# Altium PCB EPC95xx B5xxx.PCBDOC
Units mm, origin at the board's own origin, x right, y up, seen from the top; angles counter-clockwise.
Board outline 50 x 37 mm, 6 copper layers (Top Layer, Mid-Layer 1, Mid-Layer 2 (Gnd), Mid-Layer 3 (54V), Mid-Layer 4, Bottom Layer), stack 1.55 mm thick; 55 components, 32 nets, 377 pads, 537 vias.
Unrouted connection lines stored in the file: 17.
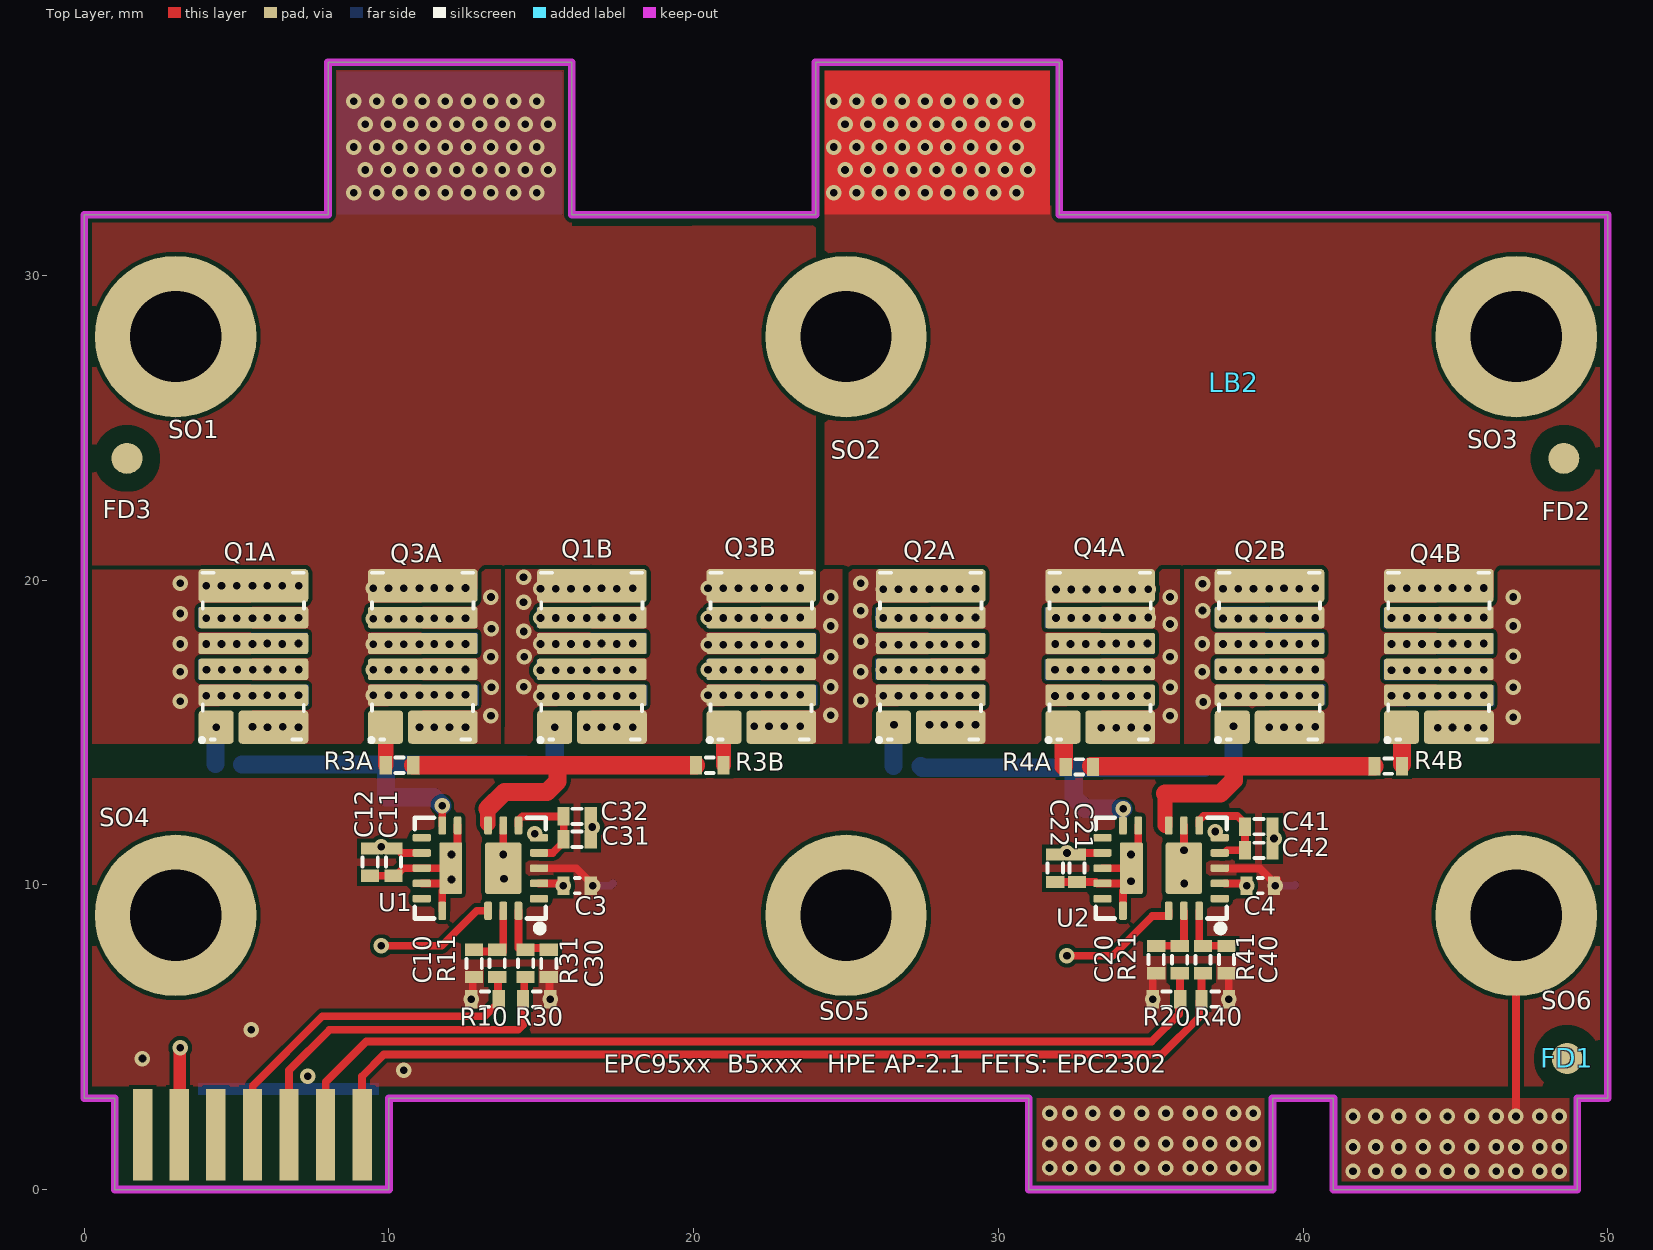
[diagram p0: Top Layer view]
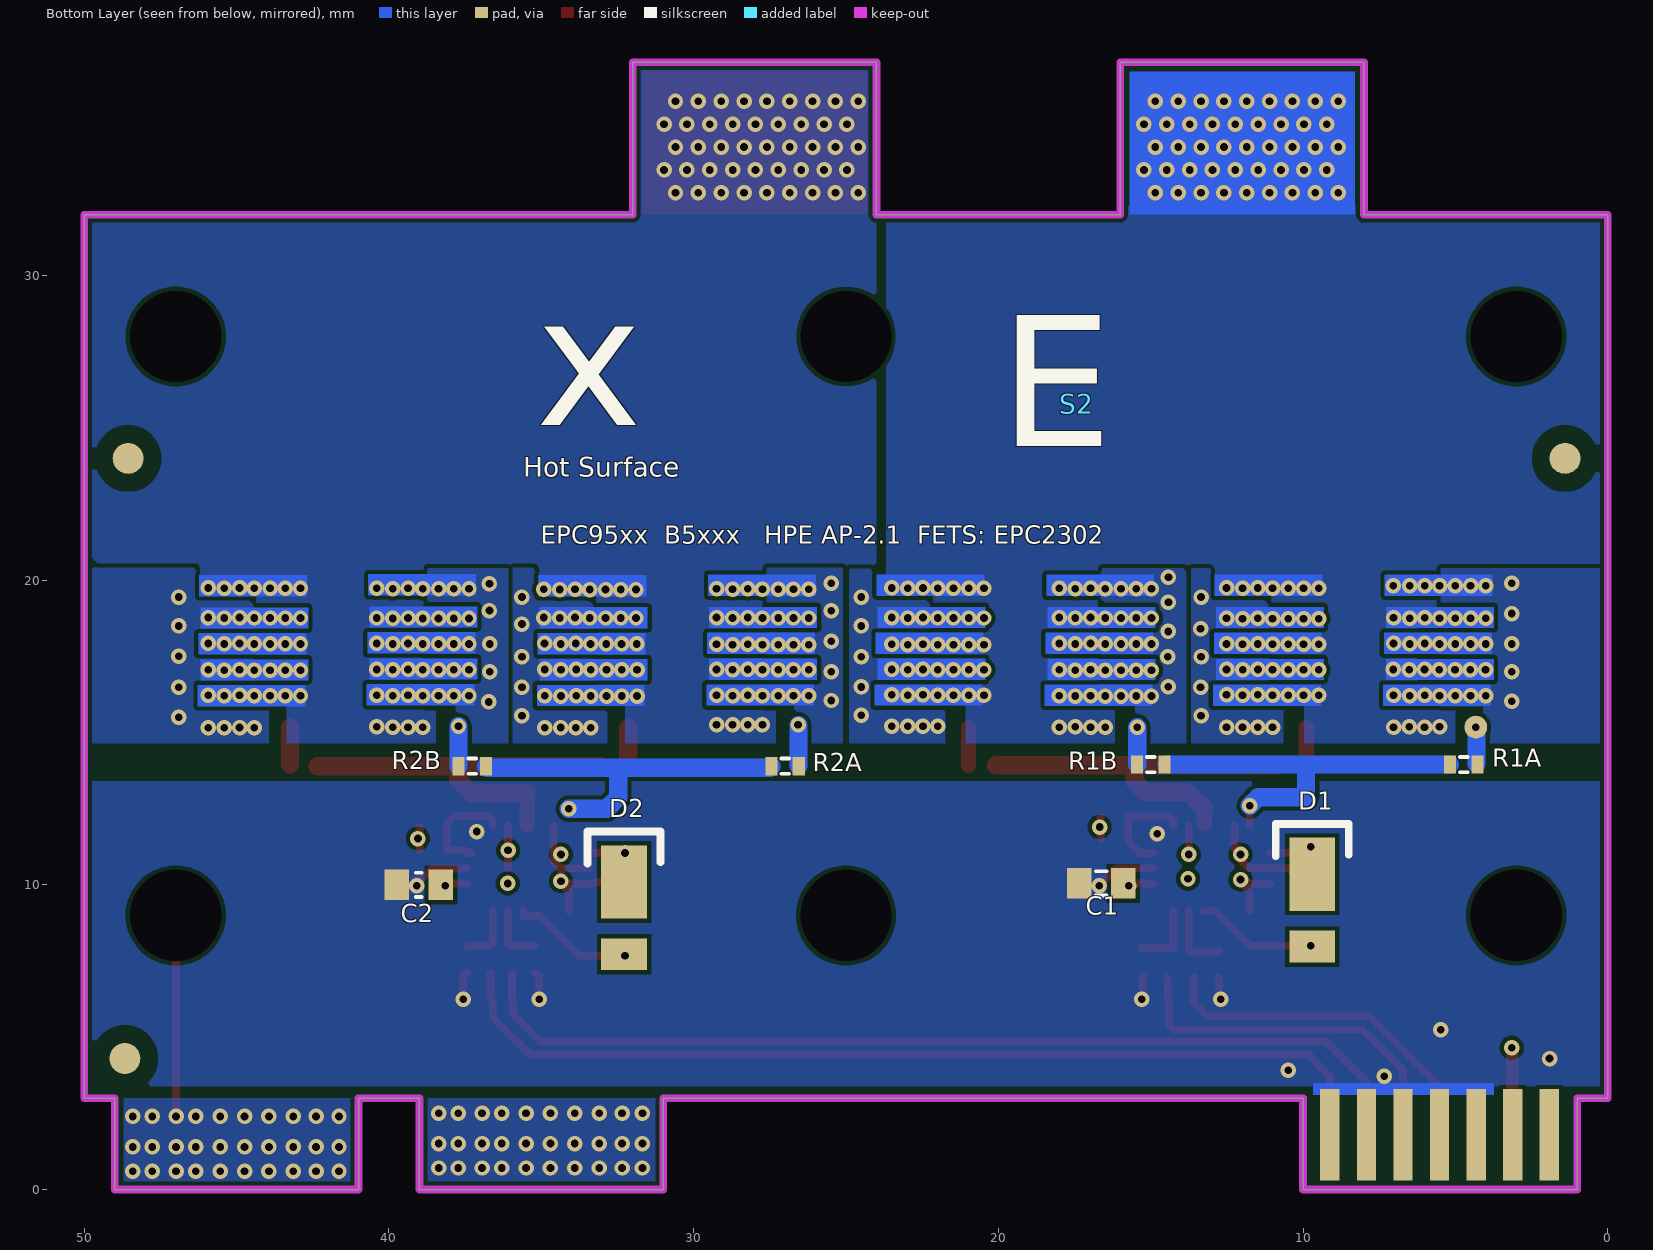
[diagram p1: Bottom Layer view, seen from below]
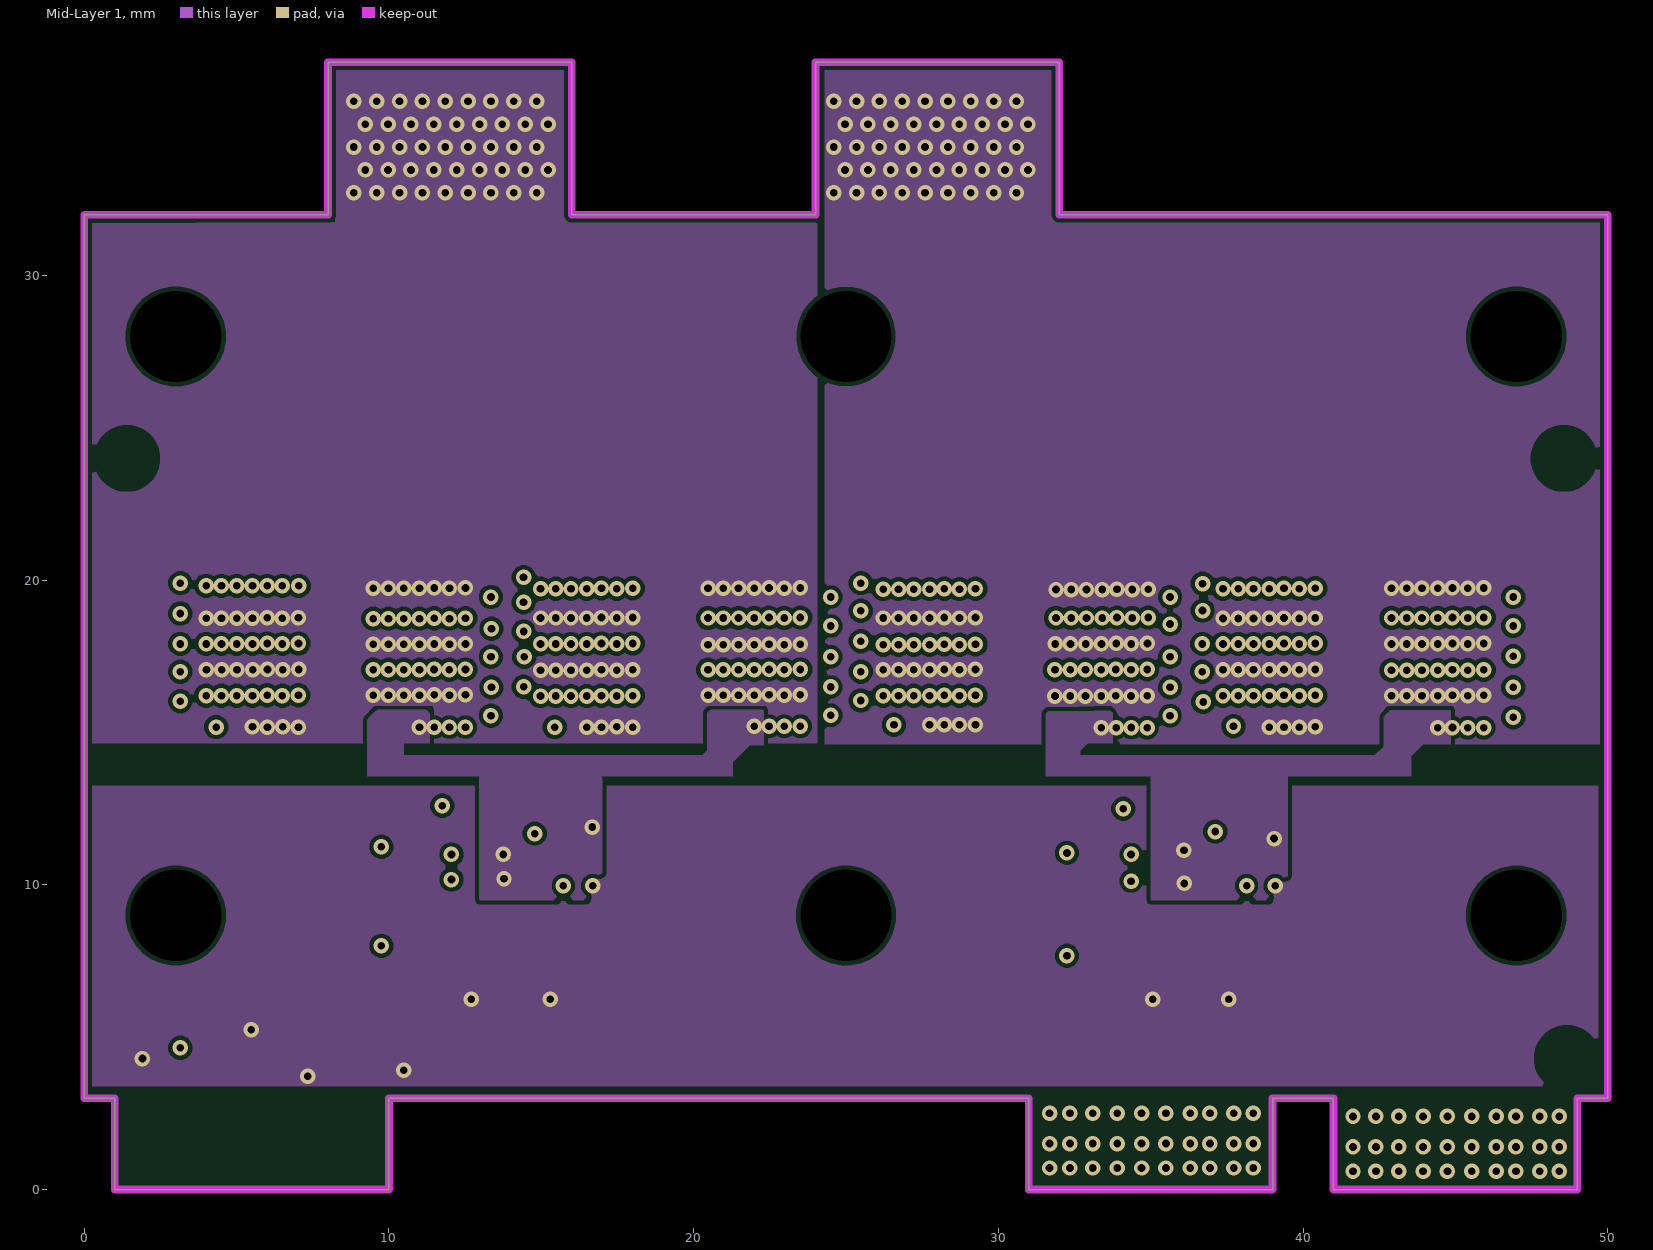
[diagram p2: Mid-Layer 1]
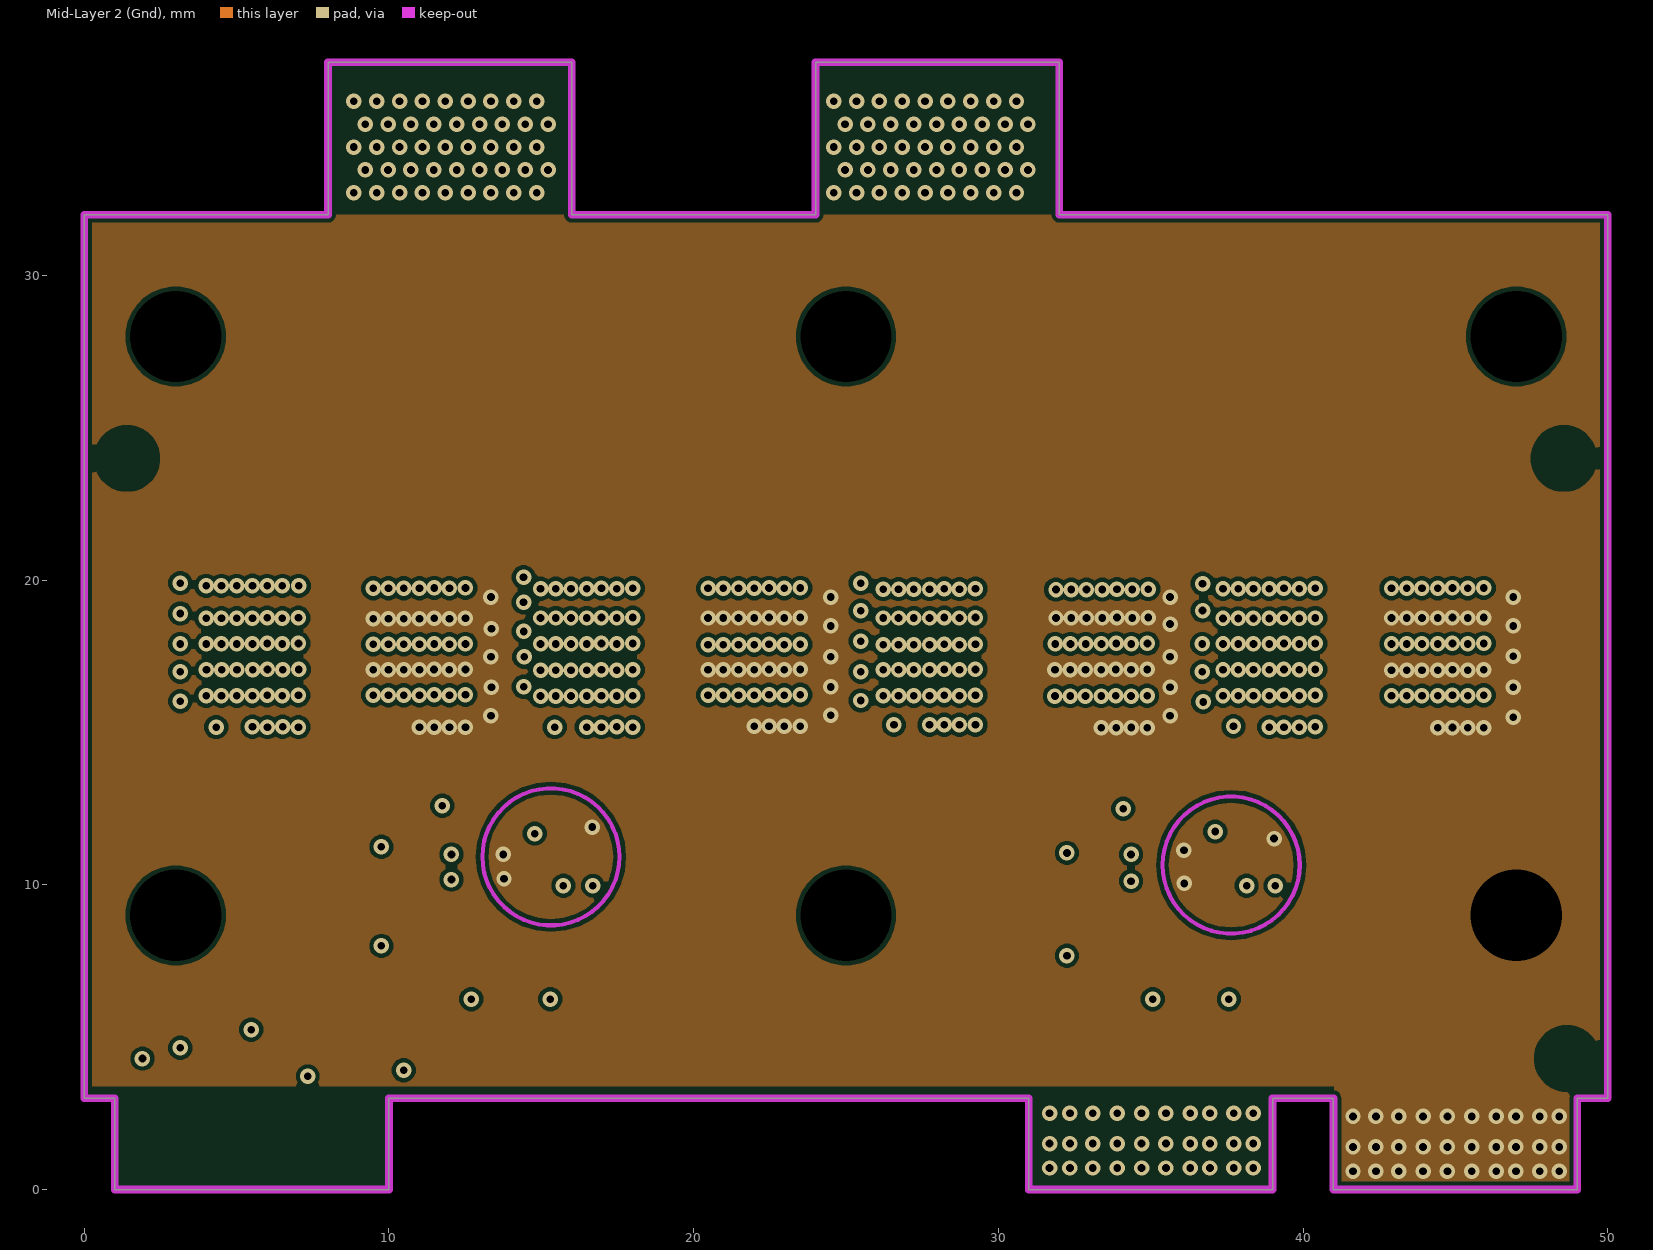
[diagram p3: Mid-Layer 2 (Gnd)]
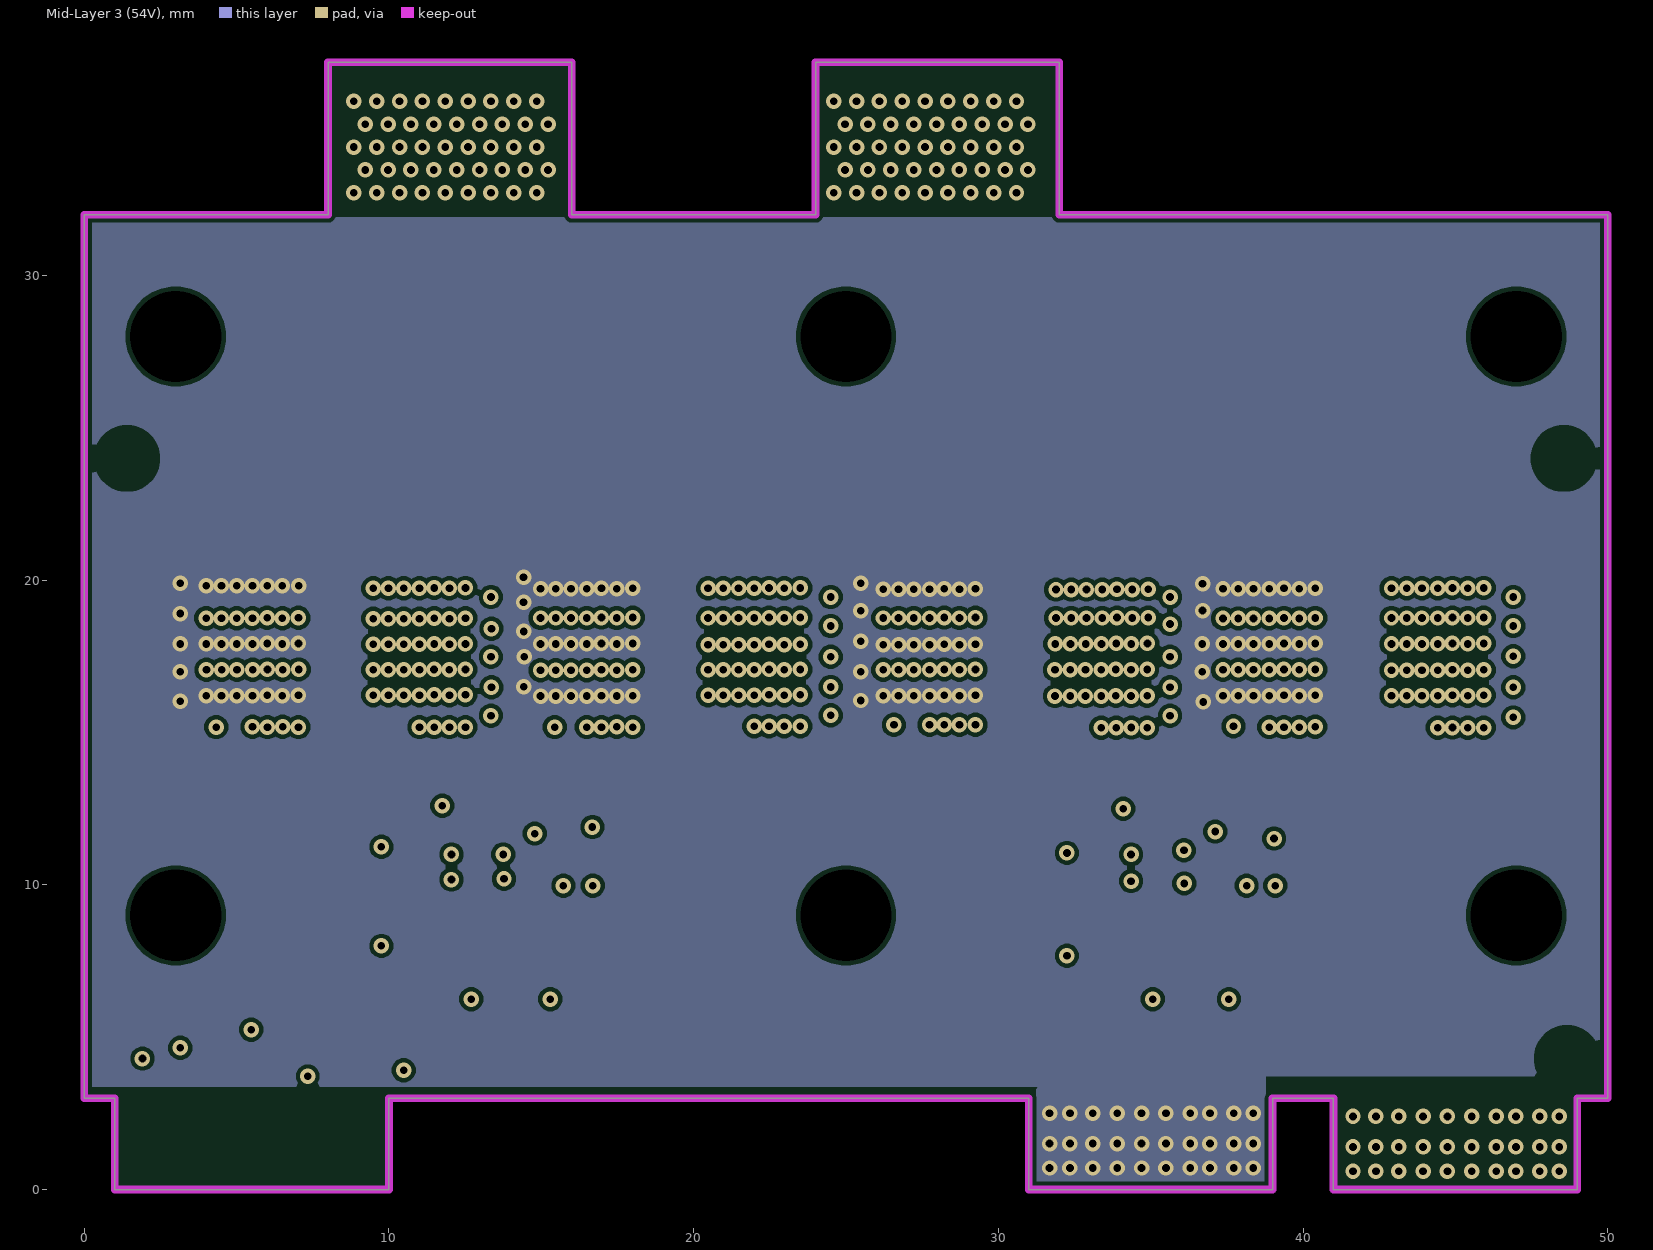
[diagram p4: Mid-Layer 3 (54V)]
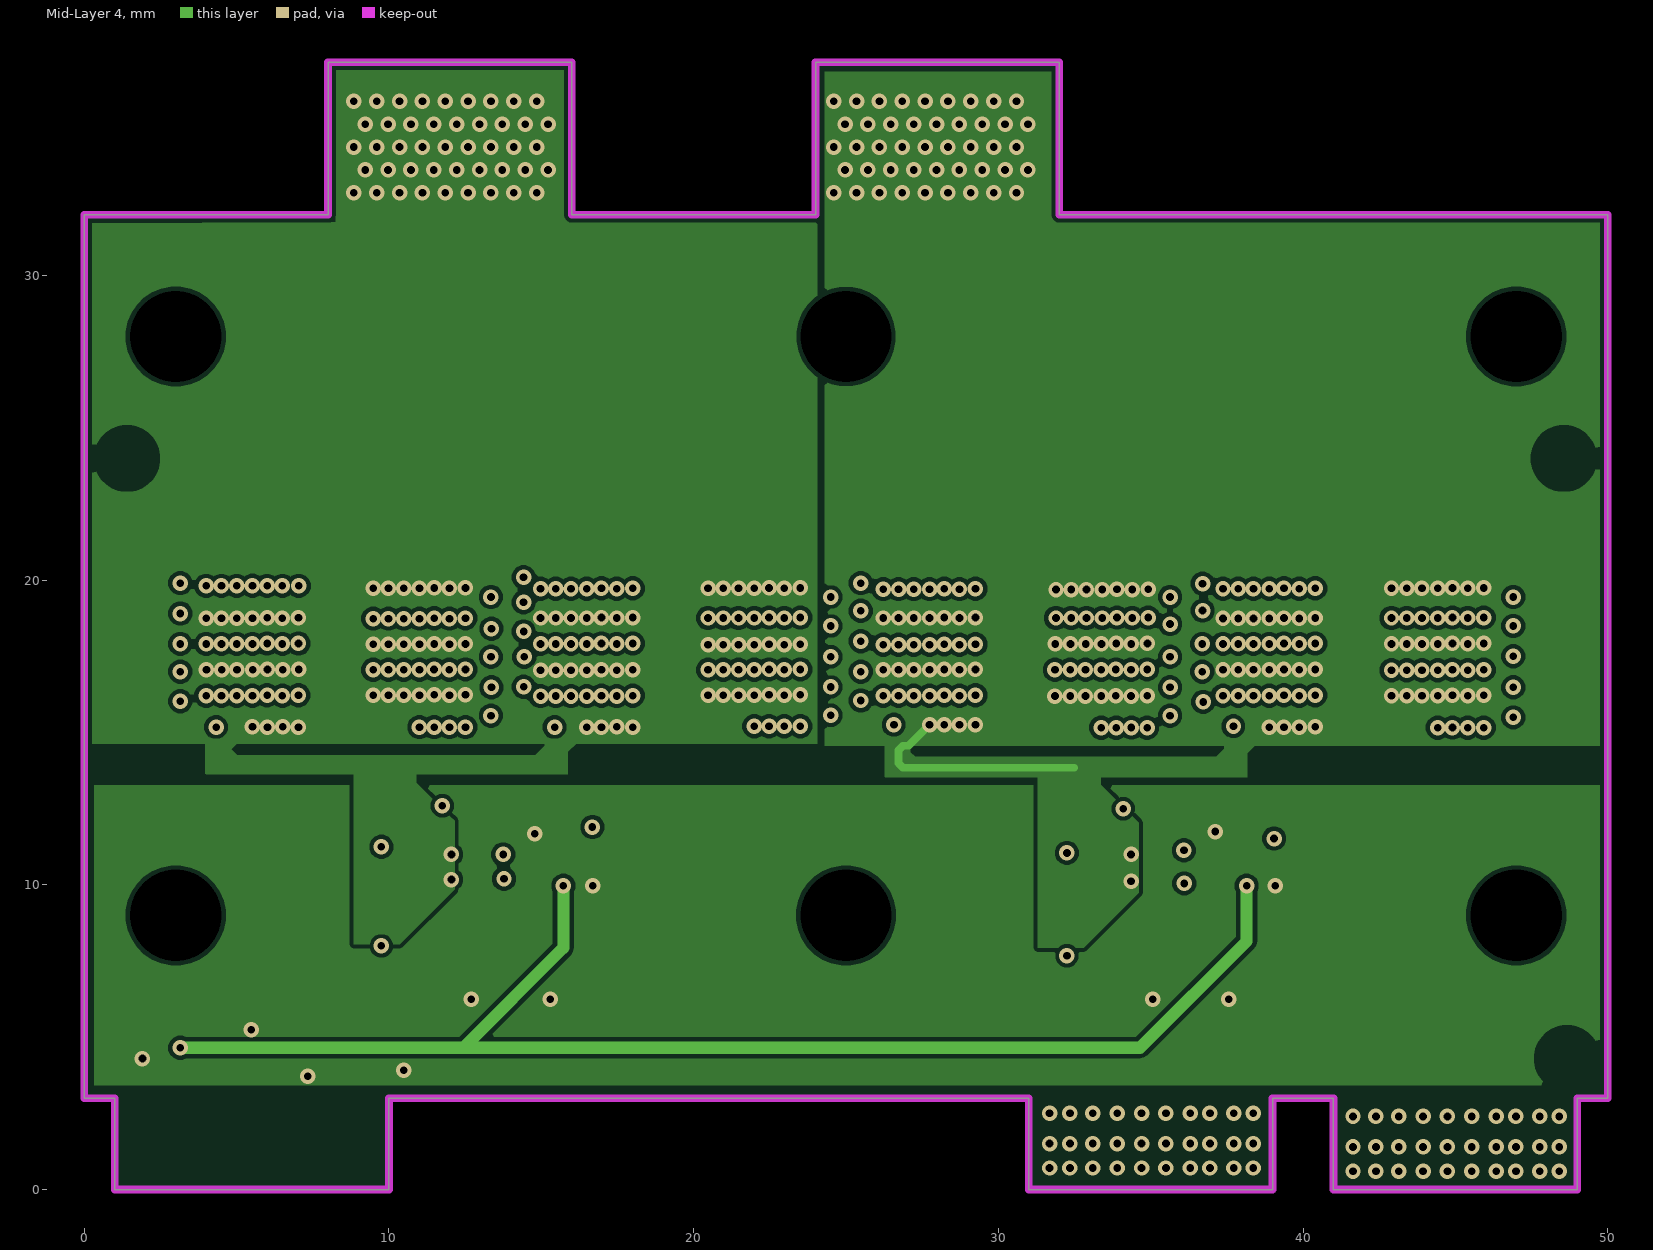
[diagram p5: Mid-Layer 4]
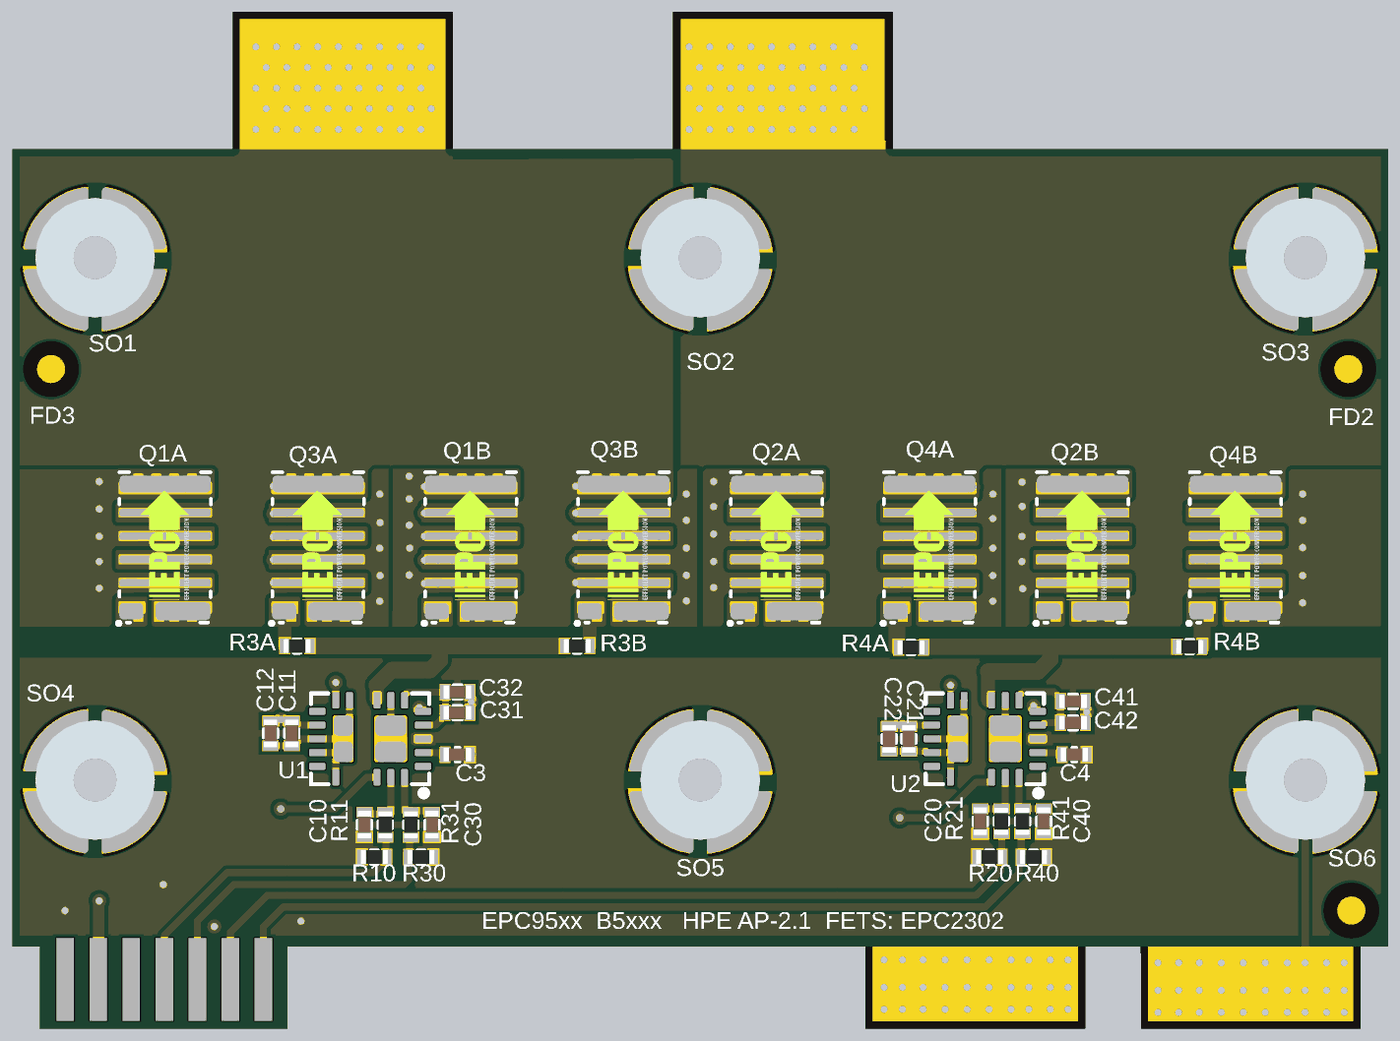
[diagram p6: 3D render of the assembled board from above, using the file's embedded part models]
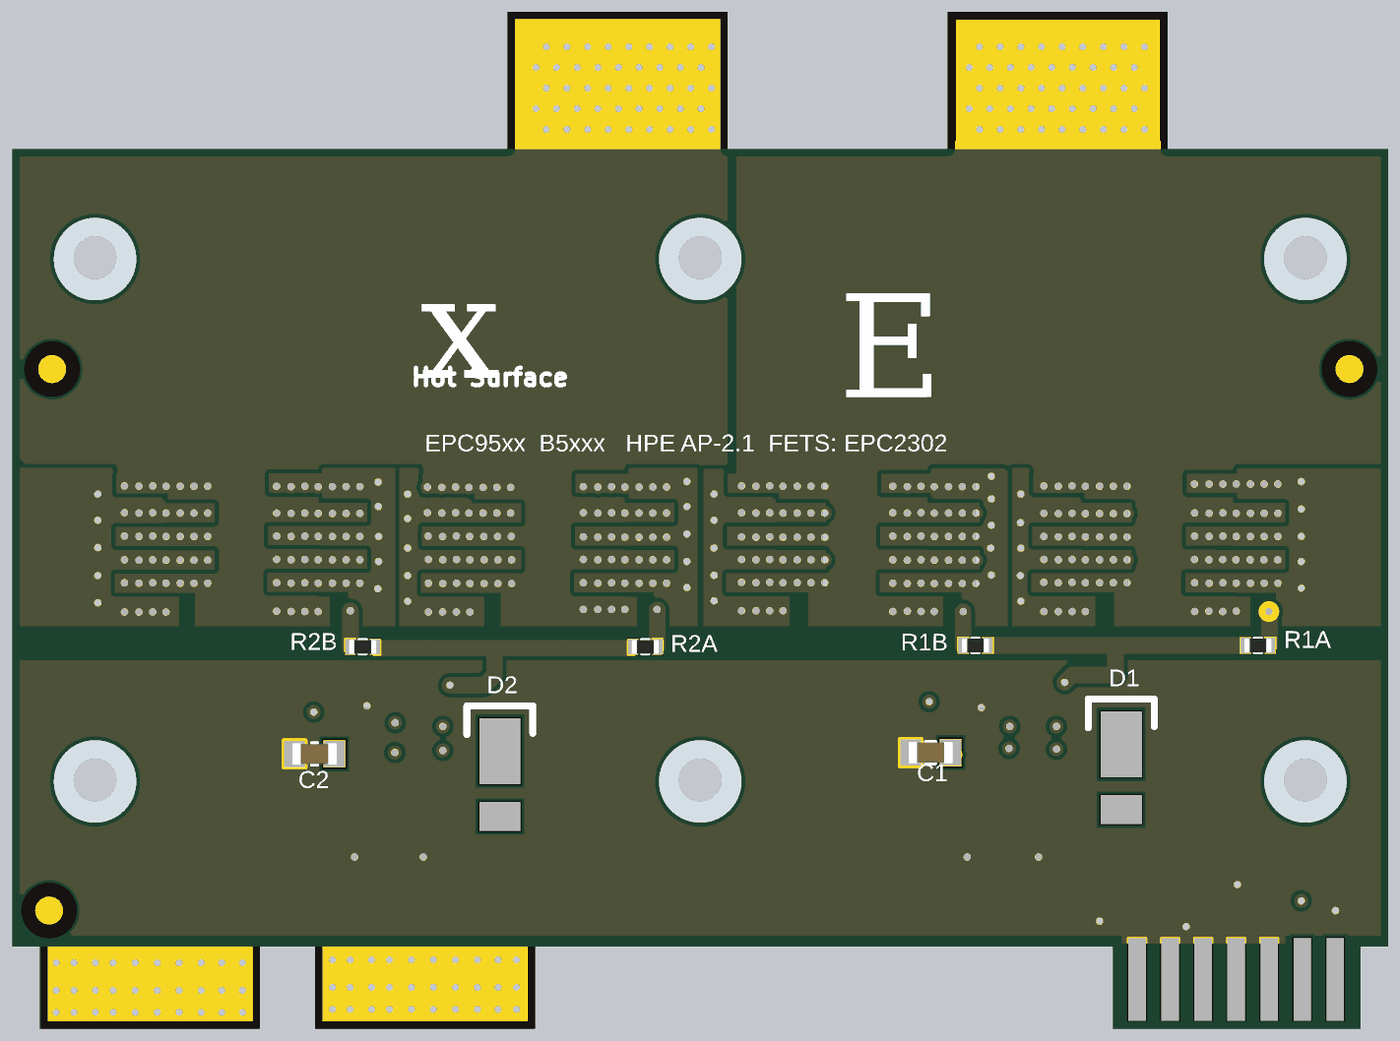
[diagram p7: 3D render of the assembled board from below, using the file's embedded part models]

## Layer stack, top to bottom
Top Solder: solder mask 0.0102, Solder Resist, Dk 3.5
Top Layer: signal copper 0.0711
Dielectric 1: core 0.127, FR-4, Dk 4.8
Mid-Layer 1: signal copper 0.0711
Dielectric 2: prepreg 0.309, PP-006, Dk 4.1
Mid-Layer 2 (Gnd): signal copper 0.07
Dielectric 3: prepreg 0.254, FR-4, Dk 4.8
Mid-Layer 3 (54V): signal copper 0.07
Dielectric 4: prepreg 0.309, PP-006, Dk 4.1
Mid-Layer 4: signal copper 0.0711
Dielectric 5: core 0.127, FR-4, Dk 4.8
Bottom Layer: signal copper 0.0711
Bottom Solder: solder mask 0.0102, Solder Resist, Dk 3.5

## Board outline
24,37 32,37 32,32 50,32 50,3 49,3 49,0 41,0 41,3 39,3 39,0 31,0 31,3 10,3 10,0 1,0 1,3 0,3 0,32 8,32 8,37 16,37 16,32 24,32

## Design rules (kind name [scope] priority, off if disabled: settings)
AssemblyTestPointUsage [All] p1 off:
AssemblyTestpoint [All] p1 off: testpointundercomponent=TRUE minsize=1.016 maxsize=2.54 preferedsize=1.524 minholesize=0 maxholesize=1.016 preferedholesize=0.813 testpointgrid=0.025 usegrid=TRUE gridtolerance=0 allowsidetop=TRUE allowsidebottom=TRUE
Clearance [All] p1: gap=0.135 ignorepadtopadclearanceinfootprint=TRUE // Everything else
Clearance Keepout [(OnLayer('Keep-Out Layer'))] p2: gap=0.508 ignorepadtopadclearanceinfootprint=TRUE except(0: Arc-Hole Track-Hole SMDPad-Hole THPad-Hole Via-Hole Fill-Hole Poly-Hole Region-Hole Text-Hole)
ComponentClearance [All] p1: gap=0.127 collisioncheckmode=3 verticalgap=0 showdistances=FALSE
FabricationTestPointUsage [All] p1 off: valid=0 allowmultiple=FALSE
FabricationTestpoint [All] p1 off: side=3 testpointundercomponent=TRUE minsize=1.016 maxsize=2.54 preferedsize=1.524 minholesize=0 maxholesize=1.016 preferedholesize=0.813 testpointgrid=0.025 allowsidetop=TRUE allowsidebottom=TRUE usegrid=TRUE gridtolerance=0
FanoutControl Fanout_BGA [IsBGA] p1 off: bgadir=Out bgaviamode=Centered fanoutstyle=Auto fanoutdirection=Alternating viagrid=0.025 // Fanout_BGA (Default Rule)
FanoutControl Fanout_LCC [IsLCC] p2 off: bgadir=Out bgaviamode=Centered fanoutstyle=Auto fanoutdirection=Alternating viagrid=0.025 // Fanout_LCC (Default Rule)
FanoutControl Fanout_SOIC [IsSOIC] p3 off: bgadir=Out bgaviamode=Centered fanoutstyle=Auto fanoutdirection=Alternating viagrid=0.025 // Fanout_SOIC (Default Rule)
FanoutControl Fanout_Small [(CompPinCount < 5)] p4 off: bgadir=Out bgaviamode=Centered fanoutstyle=Auto fanoutdirection=OutThenIn viagrid=0.025 // Fanout_Small (Default Rule)
FanoutControl Fanout_Default [All] p5 off: bgadir=Out bgaviamode=Centered fanoutstyle=Auto fanoutdirection=Alternating viagrid=0.025 // Fanout_Default (Default Rule)
HoleSize [All] p1: absolutevalues=TRUE maxlimit=3 minlimit=0.025 maxpercent=80.000 minpercent=20.000
HoleToHoleClearance [All] p1 off: gap=0.254 allowstackedmicrovias=TRUE
MinimumSolderMaskSliver [All] p1: minsoldermaskwidth=0.02
NetAntennae [All] p1 off: netantennaetolerance=0
PlaneConnect [All] p1: planeconnectstyle=Direct reliefexpansion=0.508 reliefentries=4 reliefconductorwidth=0.254 reliefairgap=0.254
PolygonConnect [All] p1: connectstyle=Direct reliefconductorwidth=0.254 reliefentries=4 polygonreliefangle="90 Angle" airgapwidth=0.254
RoomDefinition "EPC95xx B5xxx" [InComponentClass('EPC95xx B5xxx')] p1: confinementstyle=ConfineIn formatcopy=TRUE lockcomponents=FALSE outline 0,-0.3 50.35,-0.3 50.35,37 0,37
RoutingVias [All] p1: holewidth=0.711 width=1.27 viastyle="Through Hole" minholewidth=0.203 minwidth=0.254 maxholewidth=1.27 maxwidth=2.54
SilkToSilkClearance [All] p1: silktosilkclearance=0.025
SilkToSolderMaskClearance SilkscreenOverComponentPads [IsPad OR IsVia OR OnLayer('Top Solder') vs OnLayer('Top Overlay')] p1: minsilkscreentomaskgap=0.025 clearancetoexposedcopper=TRUE
SilkToSolderMaskClearance SilkscreenOverComponentPads_1 [IsPad OR IsVia OR OnLayer('Bottom Solder') vs OnLayer('Bottom Overlay')] p2: minsilkscreentomaskgap=0.025 clearancetoexposedcopper=TRUE
SolderMaskExpansion [All] p1: expansion=0.051 istentingtop=FALSE
Width [All] p1: maxlimit=254 minlimit=0.127 preferedwidth=0.254
13 further rules are at their usual default settings.

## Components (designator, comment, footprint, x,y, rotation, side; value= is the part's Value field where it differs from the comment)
C1 "C1608X5R1E106M080AC" CC0603 16.625,10.048 r180 bottom value=10uF
C2 "C1608X5R1E106M080AC" CC0603 39.024,10 r180 bottom value=10uF
C3 "UMK105ABJ474KV-F" CC0402 16.173,9.975 r180 top value=470nF
C4 "UMK105ABJ474KV-F" CC0402 38.6,9.975 r180 top value=470nF
C10 "C1005C0G2A221J050BA" CC0402 12.792,7.425 r270 top value=220pF
C11 "C1005X5R1E474K050BB" CC0402 10.15,10.75 r270 top value=470nF
C12 "C1005X5R1E105K050BC" CC0402 9.38,10.75 r270 top value=1uF
C20 "C1005C0G2A221J050BA" CC0402 35.18,7.55 r270 top value=220pF
C21 "C1005X5R1E474K050BB" CC0402 32.584,10.55 r270 top value=470nF
C22 "C1005X5R1E105K050BC" CC0402 31.867,10.55 r270 top value=1uF
C30 "C1005C0G2A221J050BA" CC0402 15.246,7.425 r270 top value=220pF
C31 "C1005X5R1E474K050BB" CC0402 16.173,11.5 r0 top value=470nF
C32 "C1005X5R1E105K050BC" CC0402 16.175,12.25 r0 top value=1uF
C40 "C1005C0G2A221J050BA" CC0402 37.488,7.55 r270 top value=220pF
C41 "C1005X5R1E474K050BB" CC0402 38.55,11.912 r0 top value=470nF
C42 "C1005X5R1E105K050BC" CC0402 38.55,11.135 r0 top value=1uF
D1 "SBR1U200P1Q" PowerDI123 9.696,9.55 r90 bottom value="200V 1A"
D2 "SBR1U200P1Q" PowerDI123 32.284,9.3 r90 bottom value="200V 1A"
FD1 "PCB Fiducial" Fiducial_Board 48.669,4.303 r0 top locked value="Fiducial 40mil"
FD2 "PCB Fiducial" Fiducial_Board 48.561,24 r0 top locked value="Fiducial 40mil"
FD3 "PCB Fiducial" Fiducial_Board 1.4,24 r0 top locked value="Fiducial 40mil"
LB2 "Hot_SIGN" Hot_SIGN 37.725,26.505 r0 top
Q1A "EPC2302" D0606_100V 5.55,17.5 r90 top locked
Q1B "EPC2302" D0606_100V 16.66,17.5 r90 top locked
Q2A "EPC2302" D0606_100V 27.78,17.5 r90 top locked
Q2B "EPC2302" D0606_100V 38.9,17.5 r90 top locked
Q3A "EPC2302" D0606_100V 11.11,17.5 r90 top locked
Q3B "EPC2302" D0606_100V 22.22,17.5 r90 top locked
Q4A "EPC2302" D0606_100V 33.34,17.5 r90 top locked
Q4B "EPC2302" D0606_100V 44.46,17.5 r90 top locked
R1A "RMCF0402FT2R0" RC0402 4.728,13.95 r180 bottom value=2.2
R1B "RMCF0402FT2R0" RC0402 14.996,13.95 r0 bottom value=2.2
R2A "RMCF0402FT2R0" RC0402 27,13.9 r180 bottom value=2.2
R2B "RMCF0402FT2R0" RC0402 37.27,13.9 r0 bottom value=2.2
R3A "RMCF0402FT2R0" RC0402 10.346,13.927 r180 top value=2.2
R3B "RMCF0402FT2R0" RC0402 20.529,13.927 r0 top value=2.2
R4A "RMCF0402FT2R0" RC0402 32.661,13.873 r180 top value=2.2
R4B "RMCF0402FT2R0" RC0402 42.797,13.9 r0 top value=2.2
R10 "ERJ-2RKF1002X" RC0402 13.15,6.25 r180 top value=10k
R11 "RC0402FR-07100RL" RC0402 13.55,7.425 r90 top value=100E
R20 "ERJ-2RKF1002X" RC0402 35.518,6.25 r180 top value=10k
R21 "RC0402FR-07100RL" RC0402 35.95,7.55 r90 top value=100E
R30 "ERJ-2RKF1002X" RC0402 14.845,6.25 r0 top value=10k
R31 "RC0402FR-07100RL" RC0402 14.483,7.425 r90 top value=100E
R40 "ERJ-2RKF1002X" RC0402 37.117,6.25 r0 top value=10k
R41 "RC0402FR-07100RL" RC0402 36.717,7.55 r90 top value=100E
S2 "AntiStat_Sign" AS_SIGN 17.431,25.8 r180 bottom
SO1 "EPC_Thermal_Spacer_SMD_M2" 9774010243R 3,28 r0 top locked value="Round Standoff M2x0.4  1.00mm"
SO2 "EPC_Thermal_Spacer_SMD_M2" 9774010243R 25,28 r0 top locked value="Round Standoff M2x0.4  1.00mm"
SO3 "EPC_Thermal_Spacer_SMD_M2" 9774010243R 47,28 r0 top locked value="Round Standoff M2x0.4  1.00mm"
SO4 "EPC_Thermal_Spacer_SMD_M2" 9774010243R 3,9 r0 top locked value="Round Standoff M2x0.4  1.00mm"
SO5 "EPC_Thermal_Spacer_SMD_M2" 9774010243R 25,9 r0 top locked value="Round Standoff M2x0.4  1.00mm"
SO6 "EPC_Thermal_Spacer_SMD_M2" 9774010243R 47,9 r0 top locked value="Round Standoff M2x0.4  1.00mm"
U1 "LMG1210RVR" WQFN-19 13,10.55 r90 top locked
U2 "LMG1210RVR" WQFN-19 35.342,10.55 r90 top locked

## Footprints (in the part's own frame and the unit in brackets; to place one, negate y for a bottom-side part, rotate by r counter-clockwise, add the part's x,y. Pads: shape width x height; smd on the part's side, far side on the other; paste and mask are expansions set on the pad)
9774010243R [mm]
  round 5.3 / inner round 0 / far side round 0 hole 3 unplated mask-2: 1(0,0)
  body extent -2.17,-2.12 2.18,2.22, height 1
AS_SIGN [mm]
CC0402 [mm] "Size 0402 Ceramic capacitor compact"
  rect 0.4x0.6 smd paste-0.025 mask+0.025: 1(-0.45,0) 2(0.45,0)
  silkscreen extent -0.08,-0.25 0.08,0.25, body extent -0.5,-0.25 0.5,0.25, height 0.53
CC0603 [mm] "Size 0402 Ceramic capacitor compact"
  rect 0.8x1 smd paste-0.025 mask+0.07: 1(-0.725,0) 2(0.725,0)
  silkscreen extent -0.18,-0.4 0.18,0.4, body extent -0.8,-0.4 0.8,0.4, height 0.83
D0606_100V [mm] "EPC2301"
  rrect20% 1.091x1.15 smd paste-1 mask-1: 1(-2.321,1.222)
  rrect20% 1.091x2.29 smd paste-1 mask-1: 2(-2.321,-0.658)
  rrect20% 0.7x3.6 smd paste-1 mask-1: 3(-1.275,0) 4(-0.425,0) 5(0.425,0) 6(1.275,0)
  rrect20% 1.091x3.6 smd paste-1 mask-1: 7(2.321,0)
  rrect25% 0.7x0.37 on Top Solder paste-1 mask-1: ""(-2.351,-0.975) ""(-2.351,-0.325) ""(-2.351,0.975) ""(2.351,-0.975) ""(2.351,-0.325) ""(2.351,0.325) ""(2.351,0.975)
  rrect25% 0.76x0.37 on Top Solder paste-1 mask-1: ""(-2.321,0.225)
  rrect50% 0.65x2 on Top Paste paste-1 mask-1: ""(-2.31,-0.64)
  rrect50% 0.6x0.875 on Top Paste paste-1 mask-1: ""(-2.31,1.237)
  rrect25% 0.47x2.075 on Top Solder paste-1 mask-1: ""(-2.175,-0.663)
  rrect25% 0.47x0.985 on Top Solder paste-1 mask-1: ""(-2.175,1.207)
  rrect25% 0.37x3.4 on Top Solder paste-1 mask-1: ""(-1.275,0) ""(-0.425,0) ""(0.425,0) ""(1.275,0)
  rrect50% 0.28x3.32 on Top Paste paste-1 mask-1: ""(-1.275,0) ""(-0.425,0) ""(0.425,0) ""(1.275,0)
  rrect25% 0.47x3.4 on Top Solder paste-1 mask-1: ""(2.175,0)
  rrect50% 0.61x3.32 on Top Paste paste-1 mask-1: ""(2.32,0)
  silkscreen extent -2.76,-1.66 2.75,1.7, body extent -2.5,-1.5 2.5,1.5, height 0.76
Fiducial_Board [mil] "Small Fiducial"
  round 40 smd paste-20 mask+20: 0(0,0)
  round 40 smd far side paste-20 mask+20: 0(0,0)
  Mid-Layer 1 pour cut-out: 0,43.31 16.57,40.01 30.62,30.62 40.01,16.57 43.31,0 43.31,0 40.01,-16.57 30.62,-30.62 16.57,-40.01 0,-43.31 0,-43.31 -16.57,-40.01 -30.62,-30.62 -40.01,-16.57 -43.31,0 -43.31,0 -40.01,16.57 -30.62,30.62 -16.57,40.01 0,43.31
  Mid-Layer 4 pour cut-out: 0,43.31 16.57,40.01 30.62,30.62 40.01,16.57 43.31,0 43.31,0 40.01,-16.57 30.62,-30.62 16.57,-40.01 0,-43.31 0,-43.31 -16.57,-40.01 -30.62,-30.62 -40.01,-16.57 -43.31,0 -43.31,0 -40.01,16.57 -30.62,30.62 -16.57,40.01 0,43.31
  Bottom Layer pour cut-out: 0,43.31 16.57,40.01 30.62,30.62 40.01,16.57 43.31,0 43.31,0 40.01,-16.57 30.62,-30.62 16.57,-40.01 0,-43.31 0,-43.31 -16.57,-40.01 -30.62,-30.62 -40.01,-16.57 -43.31,0 -43.31,0 -40.01,16.57 -30.62,30.62 -16.57,40.01 0,43.31
  Multi-Layer pour cut-out: 0,43.31 16.57,40.01 30.62,30.62 40.01,16.57 43.31,0 43.31,0 40.01,-16.57 30.62,-30.62 16.57,-40.01 0,-43.31 0,-43.31 -16.57,-40.01 -30.62,-30.62 -40.01,-16.57 -43.31,0 -43.31,0 -40.01,16.57 -30.62,30.62 -16.57,40.01 0,43.31
Hot_SIGN [mm]
PowerDI123 [mm] "PowerDI123"
  rect 1.05x1.5 smd: 1(-1.575,0)
  rect 2.4x1.5 smd: 2(0.8,0)
  silkscreen extent 1.4,-1.2 2.45,1.2, body extent -1.5,-0.95 1.5,0.95, height 1
RC0402 [mm]
  rect 0.4x0.6 smd paste-0.025 mask+0.025: 1(-0.45,0) 2(0.45,0)
  silkscreen extent -0.13,-0.25 0.13,0.25, body extent -0.5,-0.25 0.5,0.25, height 0.38
WQFN-19 [mm] "300V HB Gate Driver"
  rrect50% 0.75x0.71 on Top Paste: 0(-0.475,0.975) 0(0.475,0.975)
  rrect50% 0.75x1.13 on Top Paste: 0(-0.475,-0.75) 0(0.475,-0.75)
  rrect40% 0.25x0.6 smd paste+0 mask+0.05: 1(-1,-1.925) 2(-0.5,-1.925) 3(0,-1.925) 4(0.5,-1.925) 5(1,-1.925) 11(1,1.925) 12(0.5,1.925) 13(0,1.925) 14(-0.5,1.925) 15(-1,1.925)
  rrect40% 0.6x0.25 smd paste+0 mask+0.05: 6(1.4,-1.25) 7(1.4,-0.75) 8(1.4,-0.25) 9(1.4,0.75) 10(1.4,1.25) 16(-1.4,1.25) 17(-1.4,-0.25) 18(-1.4,-0.75) 19(-1.4,-1.25)
  rrect15% 1.7x1.2 smd paste-1.7 mask+0.05: 20(0,-0.75)
  rrect15% 1.7x0.75 smd paste-1.5 mask+0.05: 21(0,0.975)
  silkscreen extent -2.07,-2.15 1.65,2.15, body extent -1.55,-2.07 1.55,2.07, height 0.82

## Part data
C1 C2: library part C0603-10uF-25V-X5R-20%, Case Size=0603, Supplier Part Number 1=445-9015-1-ND, TempCo=X5R, Tolerance=0.2, Voltage=25
C3 C4: library part C0402-470nF-50V-X5R-10%, Case Size=0402, EPC Part Number=C-0402-056, Supplier Part Number 1=587-3497-1-ND, TempCo=X5R, Tolerance=0.1, Voltage=50
C10 C20 C30 C40: library part C0402-220pF-100V-C0G-5%, Case Size=0402, EPC Part Number=C-0402-040, Supplier Part Number 1=445-15198-1-ND, TempCo=C0G/NP0, Tolerance=0.05, Voltage=100
C11 C21 C31 C41: library part C0402-470nF-25V-X5R-10%, Case Size=0402, EPC Part Number=C-0402-054, Supplier Part Number 1=445-8020-1-ND, TempCo=X5R, Tolerance=0.1, Voltage=25
C12 C22 C32 C42: library part C0402-1uF-25V-X5R-10%, Case Size=0402, EPC Part Number=C-0402-025, Supplier Part Number 1=445-9066-1-ND, TempCo=X5R, Tolerance=0.1, Voltage=25
D1 D2: "SuperBarrier 200V 1A"
FD1 FD2 FD3: library part Fiducial_Board
LB2: library part Hot_Sign, "Hot Symbol"
Q1A Q1B Q2A Q2B Q3A Q3B Q4A Q4B: "100V 100A 1.9mE"
R1A R1B R2A R2B R3A R3B R4A R4B: library part R0402-2.2-1%-1/16W-Thickfilm, Case Size=0402, EPC Part Number=R-0402-016, Power Rating=1/16, Supplier Part Number 1=RMCF0402FT2R0CT-ND, Tolerance=0.01
R10 R20 R30 R40: library part R0402-10k-1%-0.1W-Thickfilm, Case Size=0402, EPC Part Number=R-0402-011, Power Rating=0.1, Supplier Part Number 1=P10.0KLCT-ND, Tolerance=0.01
R11 R21 R31 R41: library part R0402-100-1%-0.1W-Thickfilm, Case Size=0402, Power Rating=1/16, Supplier Part Number 1=311-100LRCT-ND, Tolerance=0.01
S2: "Anti-static caution sign"
SO1 SO2 SO3 SO4 SO5 SO6: library part EPC_SMD_Thermal_SpacerM2x1mm
U1 U2: library part LMG1210RVRT, EPC Part Number=IC-109, Supplier Part Number 1=296-53417-2-ND, Voltage Rating=300

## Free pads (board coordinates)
  rect 0.635x3 smd: 2(1.917,1.8) 2(3.117,1.8) 2(4.317,1.8) 2(5.517,1.8) 2(6.717,1.8) 2(7.918,1.8) 2(9.118,1.8)
  rect 0.635x3 smd far side: 2(1.917,1.8) 2(3.117,1.8) 2(4.317,1.8) 2(5.517,1.8) 2(6.717,1.8) 2(7.918,1.8) 2(9.118,1.8)
  round 0.75 smd far side paste-0.75 mask+0: 3(4.328,15.179)

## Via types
v1: diameter 0.508, hole 0.254, Top Layer to Bottom Layer, tented both sides, 447 vias
v2: diameter 0.508, hole 0.254, Top Layer to Bottom Layer, 90 vias

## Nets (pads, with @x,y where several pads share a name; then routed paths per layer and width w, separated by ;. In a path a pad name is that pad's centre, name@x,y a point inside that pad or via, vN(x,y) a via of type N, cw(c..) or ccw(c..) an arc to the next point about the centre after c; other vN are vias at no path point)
GateHSA: R1A.1 R1B.1 U1.10 | length 13
  Top Layer w0.254: U1.10 v1(11.75,12.6)
  Bottom Layer w0.6: R1A.1 9.902,13.95 ; v1(11.75,12.6) 11.476,12.874 9.902,12.874 9.902,13.95 ; R1B.1@14.483,13.95 9.902,13.95
GateHSB: R2A.1 R2B.1 U2.10 | length 12.2
  Bottom Layer w0.254: 32.809,12.457 32.852,12.5
  Bottom Layer w0.6: R2A.1 27.5,13.85 32.479,13.85 ; v1(34.1,12.5) 32.852,12.5 32.479,12.874 32.479,13.85 ; R2B.1 36.769,13.85 32.479,13.85
GateLSA: R3A.1 R3B.1 U1.8 | length 13
  Top Layer w0.5: U1.8@13.24,12 13.24,12.5
  Top Layer w0.6: R3A.1 15.531,13.927 ; 13.24,12.5 13.789,13.049 15.179,13.049 15.531,13.401 15.531,13.927 ; R3B.1 15.531,13.927
GateLSB: R4A.1 R4B.1 U2.8 | length 13.3
  Top Layer w0.254: 37.698,13.9 37.725,13.873
  Top Layer w0.5: 35.467,11.95 35.467,13
  Top Layer w0.6: R4A.1@33.05,13.9 37.698,13.9 R4B.1 ; 35.467,13 37.291,13 37.725,13.434 37.725,13.873
NetC10_1: C10.1 R11.2 U1.18 | length 2.3
  Top Layer w0.254: C10.1@12.745,7.818 13.748,7.818 U1.18 U1.18
NetC11_1: C11.1 C12.1 D1.2 U1.12 | length 1.8
  Top Layer w0.254: C12.1@9.38,11.2 9.75,11.2 10.15,11.2 10.25,11.2 10.4,11.05 U1.12
  other v1: 9.75,11.25
NetC20_1: C20.1 R21.2 U2.18 | length 2
  Top Layer w0.254: C20.1@35.218,8 R21.2 36.019,8 36.092,8.073 U2.18
NetC21_1: C21.1 C22.1 D2.2 U2.12 | length 1.6
  Top Layer w0.254: C22.1 32.25,11 C21.1 32.632,11.048 33.415,11.048 U2.12
  other v1: 32.25,11.05
NetC30_1: C30.1 R31.2 U1.19 | length 2.3
  Top Layer w0.254: U1.19 14.25,7.929 C30.1@15.298,7.929
NetC40_1: C40.1 R41.2 U2.19 | length 2
  Top Layer w0.254: U2.19 36.592,8.073 36.665,8 37.388,8 C40.1@37.422,7.966 ; C40.1@37.422,8 C40.1@37.422,7.966 ; C40.1@37.438,7.95 C40.1@37.422,7.966
NetD1_1: D1.1 U1.17 | length 4
  Top Layer w0.254: v1(9.75,8) 11.731,8 12.881,9.15 U1.17
NetD2_1: D2.1 U2.17 | length 4.1
  Top Layer w0.254: v1(32.25,7.675) 33.751,7.675 35.053,8.977 35.59,8.977 35.592,8.979 U2.17
NetQ1A_1: pad.3 Q1A.1 R1A.2 | length 1.2
  Bottom Layer w0.254: R1A.2 R1A.2@4.303,13.975 ; pad.3@4.303,15.154 v1(4.328,15.179)
  Bottom Layer w0.6: R1A.2@4.303,13.975 pad.3@4.303,15.154
NetQ1B_1: Q1B.1 R1B.2 | length 1.2
  Bottom Layer w0.254: v1(15.438,15.179) v1@15.442,15.175 ; R1B.2@15.442,13.954 R1B.2
  Bottom Layer w0.6: R1B.2@15.442,13.954 v1@15.442,15.175
NetQ2A_1: Q2A.1 R2A.2 | length 1.4
  Bottom Layer w0.254: R2A.2 R2A.2@26.561,13.911 ; v1@26.561,15.245 v1(26.572,15.256)
  Bottom Layer w0.6: R2A.2@26.561,13.911 v1@26.561,15.245
NetQ2B_1: Q2B.1 R2B.2 | length 1.3
  Bottom Layer w0.6: R2B.2 v1(37.719,15.208)
NetQ3A_1: Q3A.1 R3A.2 | length 1.3
  Top Layer w0.254: Q3A.1 Q3A.1@9.896,15.171
  Top Layer w0.5: R3A.2 Q3A.1@9.896,15.171
NetQ3B_1: Q3B.1 R3B.2 | length 1.3
  Top Layer w0.254: Q3B.1@20.979,15.16 Q3B.1
  Top Layer w0.5: R3B.2 Q3B.1@20.979,15.16
NetQ4A_1: Q4A.1 R4A.2 | length 1.3
  Top Layer w0.254: Q4A.1 Q4A.1@32.15,15.147
  Top Layer w0.6: R4A.2@32.15,13.9 Q4A.1@32.15,15.147
NetQ4B_1: Q4B.1 R4B.2 | length 1.3
  Top Layer w0.254: Q4B.1 Q4B.1@43.247,15.17 ; R4B.2@43.247,13.95 R4B.2@43.299,13.897
  Top Layer w0.6: R4B.2@43.247,13.95 Q4B.1@43.247,15.17
PRE_54V: Q1A.3 Q1A.5 Q1A.7 Q1B.3 Q1B.5 Q1B.7 Q2A.3 Q2A.5 Q2A.7 Q2B.3 Q2B.5 Q2B.7
  other v1: 31.683,0.709 32.351,0.709 33.1,0.709 33.9,0.709 34.7,0.709 35.5,0.709 36.3,0.709 36.946,0.709 37.725,0.709 38.369,0.709 31.683,1.509 32.351,1.509 33.1,1.509 33.9,1.509 34.7,1.509 35.5,1.509 36.3,1.509 36.946,1.509 37.725,1.509 38.369,1.509 31.683,2.509 32.351,2.509 33.1,2.509 33.9,2.509 34.7,2.509 35.5,2.509 36.3,2.509 36.946,2.509 37.725,2.509 38.369,2.509 36.723,16.007 3.15,16.028 25.487,16.054 4,16.211 4.5,16.211 5,16.211 5.517,16.211 6.5,16.211 14.974,16.197 15.474,16.197 15.974,16.197 16.491,16.197 16.974,16.211 17.474,16.197 18,16.211 26.224,16.211 26.724,16.211 27.224,16.211 27.741,16.211 28.724,16.211 37.374,16.211 37.874,16.211 38.374,16.211 38.891,16.211 39.874,16.211 6,16.225 7.026,16.225 28.224,16.225 29.25,16.225 39.374,16.225 40.4,16.225 14.419,16.505 3.15,17 25.487,17 36.694,17 14.44,17.487 26.224,17.884 26.724,17.884 27.224,17.884 27.741,17.884 28.724,17.884 3.15,17.911 4,17.911 4.5,17.911 5,17.911 5.517,17.911 6.5,17.911 14.974,17.911 15.474,17.911 15.974,17.911 16.491,17.911 17.474,17.911 28.224,17.897 29.25,17.897 36.694,17.911 37.374,17.911 37.874,17.911 38.374,17.911 38.891,17.911 39.874,17.911 6,17.925 7.026,17.925 16.974,17.925 18,17.925 39.374,17.925 40.4,17.925 25.487,18 14.419,18.32 3.15,18.908 25.487,18.998 36.704,19.005 14.418,19.276 14.974,19.722 15.474,19.722 15.974,19.722 16.491,19.722 17.474,19.722 26.224,19.709 26.724,19.709 27.224,19.709 27.741,19.709 28.224,19.722 28.724,19.709 29.25,19.722 37.374,19.722 37.874,19.722 38.374,19.722 38.891,19.722 39.874,19.722 16.974,19.736 18,19.736 39.374,19.736 40.4,19.736 4,19.816 4.5,19.816 5,19.816 5.517,19.821 6,19.816 6.5,19.816 7.035,19.816 36.704,19.887 3.15,19.906 25.487,19.906 14.418,20.1
S12V: C1.2 C2.2 C3.2 C4.2 pad.2@3.117,1.8 U1.2 U2.2 | length 49.4
  Top Layer w0.254: U1.2 14.927,10.048 15.65,10.048 v1(15.723,9.975) ; U2.2@37.44,10.048 38.077,10.048 v1(38.15,9.975)
  Top Layer w0.4: pad.2@3.117,1.8 3.134,1.816 3.134,4.638 v1(3.15,4.655)
  Mid-Layer 4 w0.4: v1(3.15,4.655) 12.442,4.655 ; v1(15.723,9.975) 15.723,7.936 12.442,4.655 ; v1(38.15,9.975) 38.15,8.154 34.65,4.655 12.442,4.655
SEC_RTN: C31.2 C32.2 C41.2 C42.2 Q3A.2 Q3A.4 Q3A.6 Q3B.2 Q3B.4 Q3B.6 Q4A.2 Q4A.4 Q4A.6 Q4B.2 Q4B.4 Q4B.6 SO6.1 U1.7 U1.20 U2.7 U2.20 | length 10.4
  Top Layer w0.254: v1(13.748,11) 13.75,11.002 U1.7 ; C31.2 16.637,11.513 16.637,11.887 16.65,11.9 C32.2@16.65,12.2 ; U2.20 U2.7 ; C42.2 C41.2 ; v1(46.988,2.4) 46.994,2.406 46.994,8.994 SO6.1
  other v1: 41.641,0.6 42.393,0.6 43.142,0.6 43.942,0.6 44.742,0.6 45.542,0.6 46.342,0.6 46.988,0.6 47.767,0.6 48.411,0.6 41.641,1.4 42.393,1.4 43.142,1.4 43.942,1.4 44.742,1.4 45.542,1.4 46.342,1.4 46.988,1.4 47.767,1.4 48.411,1.4 41.641,2.4 42.393,2.4 43.142,2.4 43.942,2.4 44.742,2.4 45.542,2.4 46.342,2.4 47.767,2.4 48.411,2.4 36.102,10.05 13.775,10.2 36.092,11.135 39.05,11.523 16.675,11.9 33.375,15.161 33.867,15.161 34.367,15.163 34.884,15.161 44.422,15.161 44.905,15.163 45.405,15.161 45.931,15.161 11,15.179 11.483,15.179 11.983,15.179 12.507,15.179 21.991,15.208 22.474,15.208 22.974,15.208 23.5,15.208 46.9,15.5 13.346,15.556 35.638,15.556 24.496,15.568 13.361,16.487 35.638,16.487 46.9,16.487 24.496,16.5 42.905,17.047 43.405,17.047 43.905,17.047 44.422,17.047 45.405,17.047 9.481,17.061 9.981,17.061 10.481,17.061 10.998,17.061 11.481,17.075 11.981,17.061 12.507,17.075 20.474,17.061 20.974,17.061 21.474,17.061 21.991,17.061 22.474,17.075 22.974,17.061 23.5,17.075 31.858,17.061 32.358,17.061 32.858,17.061 33.375,17.061 33.858,17.075 34.358,17.061 34.884,17.075 44.905,17.061 45.931,17.061 13.346,17.487 24.496,17.488 35.638,17.487 46.9,17.506 13.361,18.411 24.496,18.5 46.9,18.5 35.638,18.562 9.483,18.741 9.983,18.741 10.483,18.741 11,18.741 11.483,18.754 11.983,18.741 12.509,18.754 20.474,18.761 20.974,18.761 21.474,18.761 21.991,18.761 22.474,18.775 22.974,18.761 23.5,18.775 31.893,18.761 32.393,18.761 32.893,18.761 33.41,18.761 33.893,18.775 34.393,18.761 34.919,18.775 42.905,18.761 43.405,18.761 43.905,18.761 44.422,18.761 44.905,18.775 45.405,18.761 45.931,18.775 13.346,19.45 24.496,19.45 35.638,19.45 46.9,19.45
SEC_SR1: C11.2 C12.2 Q1A.2 Q1A.4 Q1A.6 Q1B.2 Q1B.4 Q1B.6 Q3A.3 Q3A.5 Q3A.7 Q3B.3 Q3B.5 Q3B.7 U1.9 U1.13 U1.14 U1.16 U1.21 | length 6.3
  Top Layer w0.254: C12.2 C11.2 10.25,10.3 10.323,10.373 10.323,10.401 10.472,10.55 U1.13 11.777,10.55 12.05,10.823 v1(12.05,11.002) 12.248,11.2 12.248,11.948 U1.9 ; U1.14 11.925,10.05 v1(12.05,10.175) 12.05,10.1 11.752,9.802 11.752,9.152 U1.16
  other v1: 5.517,15.193 6.009,15.179 6.509,15.193 7.026,15.179 16.491,15.179 16.974,15.179 17.474,15.193 18,15.179 9.483,16.227 9.983,16.227 10.483,16.227 11,16.227 11.483,16.241 11.983,16.227 12.509,16.241 20.474,16.227 20.974,16.227 21.474,16.227 21.991,16.227 22.474,16.241 22.974,16.227 23.5,16.241 14.974,17.047 15.474,17.047 15.974,17.047 16.491,17.047 17.474,17.047 4.009,17.061 4.509,17.061 5.009,17.061 5.526,17.061 6.009,17.075 6.509,17.061 7.035,17.075 16.974,17.061 18,17.061 20.474,17.884 20.974,17.884 21.474,17.884 21.991,17.884 22.974,17.884 9.483,17.897 9.983,17.897 10.483,17.897 11,17.897 11.483,17.911 11.983,17.897 12.509,17.911 22.474,17.897 23.5,17.897 4,18.754 4.5,18.754 5,18.754 5.517,18.754 6.5,18.754 6,18.768 7.026,18.768 14.974,18.761 15.474,18.761 15.974,18.761 16.491,18.761 16.974,18.775 17.474,18.761 18,18.775 9.483,19.736 9.983,19.736 10.483,19.736 11,19.736 11.983,19.736 20.474,19.736 20.974,19.736 21.474,19.736 21.991,19.736 22.974,19.736 11.483,19.75 12.509,19.75 22.474,19.75 23.5,19.75
  other v2: 8.846,32.719 9.596,32.719 10.346,32.719 11.096,32.719 11.846,32.719 12.596,32.719 13.346,32.719 14.096,32.719 14.846,32.719 9.221,33.469 9.971,33.469 10.721,33.469 11.471,33.469 12.221,33.469 12.971,33.469 13.721,33.469 14.471,33.469 15.221,33.469 8.846,34.219 9.596,34.219 10.346,34.219 11.096,34.219 11.846,34.219 12.596,34.219 13.346,34.219 14.096,34.219 14.846,34.219 9.221,34.969 9.971,34.969 10.721,34.969 11.471,34.969 12.221,34.969 12.971,34.969 13.721,34.969 14.471,34.969 15.221,34.969 8.846,35.719 9.596,35.719 10.346,35.719 11.096,35.719 11.846,35.719 12.596,35.719 13.346,35.719 14.096,35.719 14.846,35.719
SEC_SR2: C21.2 C22.2 Q2A.2 Q2A.4 Q2A.6 Q2B.2 Q2B.4 Q2B.6 Q4A.3 Q4A.5 Q4A.7 Q4B.3 Q4B.5 Q4B.7 U2.9 U2.13 U2.14 U2.16 U2.21 | length 14.2
  Top Layer w0.254: C22.2 C21.2 33.196,10.1 33.246,10.05 U2.14 34.119,10.05 U2.21@34.367,10.298 ; U2.13 U2.21 ; U2.16 34.094,9.152 34.094,9.802 34.367,10.075 U2.21@34.367,10.298 ; U2.9 34.59,11.948 34.59,10.773 U2.21 ; U2.21@34.367,10.298 U2.21
  Mid-Layer 4 w0.254: v1(27.741,15.256) 27.052,14.567 26.873,14.567 26.724,14.419 26.724,13.999 26.873,13.85 32.488,13.85
  other v1: 34.358,10.125 34.358,11 38.891,15.179 39.374,15.179 39.874,15.179 40.4,15.193 28.224,15.256 28.724,15.256 29.25,15.256 31.858,16.197 32.358,16.197 32.858,16.197 33.375,16.197 33.858,16.211 34.358,16.197 34.884,16.211 42.905,16.211 43.405,16.211 43.905,16.211 44.422,16.211 45.405,16.211 44.905,16.225 45.931,16.225 26.224,17.061 26.724,17.061 27.224,17.061 27.741,17.061 28.224,17.075 28.724,17.061 29.25,17.075 37.374,17.061 37.874,17.061 38.374,17.061 38.891,17.061 39.374,17.075 39.874,17.061 40.4,17.075 31.867,17.911 32.367,17.911 32.867,17.911 33.384,17.911 34.367,17.911 42.905,17.911 43.405,17.911 43.905,17.911 44.422,17.911 45.405,17.911 33.867,17.925 34.893,17.925 44.905,17.925 45.931,17.925 37.374,18.747 37.874,18.747 38.374,18.747 38.891,18.747 39.874,18.747 26.224,18.761 26.724,18.761 27.224,18.761 27.741,18.761 28.224,18.775 28.724,18.761 29.25,18.775 39.374,18.761 40.4,18.761 31.893,19.695 32.393,19.695 32.893,19.695 33.41,19.695 34.393,19.695 33.893,19.709 34.919,19.709 42.905,19.736 43.405,19.736 43.905,19.736 44.422,19.736 45.405,19.736 44.905,19.75 45.931,19.75
  other v2: 24.596,32.719 25.346,32.719 26.096,32.719 26.846,32.719 27.596,32.719 28.346,32.719 29.096,32.719 29.846,32.719 30.596,32.719 24.971,33.469 25.721,33.469 26.471,33.469 27.221,33.469 27.971,33.469 28.721,33.469 29.471,33.469 30.221,33.469 30.971,33.469 24.596,34.219 25.346,34.219 26.096,34.219 26.846,34.219 27.596,34.219 28.346,34.219 29.096,34.219 29.846,34.219 30.596,34.219 24.971,34.969 25.721,34.969 26.471,34.969 27.221,34.969 27.971,34.969 28.721,34.969 29.471,34.969 30.221,34.969 30.971,34.969 24.596,35.719 25.346,35.719 26.096,35.719 26.846,35.719 27.596,35.719 28.346,35.719 29.096,35.719 29.846,35.719 30.596,35.719
SGND: C1.1 C2.1 C3.1 C4.1 C10.2 C20.2 C30.2 C40.2 pad.2@4.317,1.8 pad.2@5.517,1.8 pad.2@6.717,1.8 pad.2@7.918,1.8 pad.2@9.118,1.8 R10.2 R20.2 R30.2 R40.2 U1.3 U1.5 U2.3 U2.5 | length 15
  Top Layer w0.254: v1(12.7,6.25) 12.746,6.296 12.746,6.929 C10.2 ; U1.3 16.148,10.55 16.689,10.009 v1(16.689,9.975) ; C30.2@15.246,7 15.27,6.976 15.27,6.274 v1(15.295,6.25) ; v1(35.068,6.25) 35.068,7.027 35.141,7.1 C20.2@35.218,7.1 ; C40.2@37.422,7.1 37.494,7.1 37.567,7.027 v1(37.567,6.25) ; U2.3@37.44,10.548 37.488,10.548 37.499,10.537 38.588,10.537 39.05,10.075 C4.1 ; C4.1@39.069,10.094 C4.1@39.088,10.113 ; v1(39.088,9.975) C4.1@39.088,10.113 ; C4.1@39.088,10.174 C4.1@39.088,10.113 ; C4.1@39.149,10.174 C4.1@39.088,10.113
  Bottom Layer w0.254: pad.2@4.317,1.8 pad.2@4.317,2.982 ; pad.2@5.517,1.8 pad.2@5.517,2.982 ; pad.2@6.717,1.8 pad.2@6.717,2.982 ; pad.2@7.918,1.8 pad.2@7.918,2.982 ; pad.2@9.118,1.8 pad.2@9.118,2.982 ; v1(16.689,9.975) 17.277,9.975 C1.1 ; v1(39.088,9.975) 39.724,9.975 C2.1
  other v1: 7.336,3.722 10.481,3.918 1.908,4.3 5.477,5.25 14.783,11.684 37.117,11.75
SR_HSDRV1: pad.2@5.517,1.8 R10.1 R11.1 | length 11.7
  Top Layer w0.254: pad.2@5.526,1.75 5.517,1.759 5.517,1.8 5.526,1.809 5.526,3.401 7.814,5.688 13.138,5.688 13.6,6.15 R10.1 13.575,6.275 13.575,6.95 R11.1
SR_HSDRV2: pad.2@7.918,1.8 R20.1 R21.1 | length 32
  Top Layer w0.254: pad.2@7.918,1.8 7.925,1.807 7.925,3.532 9.254,4.861 35.029,4.861 ; 35.037,4.865 35.93,5.758 35.93,6.212 R20.1 35.959,6.259 35.959,7.091 R21.1
SR_LSDRV1: pad.2@6.717,1.8 R30.1 R31.1 | length 12
  Top Layer w0.254: pad.2@6.717,1.8 6.717,3.917 8.05,5.25 14.246,5.25 14.395,5.399 R30.1 14.439,6.294 14.439,6.931 R31.1
SR_LSDRV2: pad.2@9.118,1.8 R40.1 R41.1 | length 31.7
  Top Layer w0.254: pad.2@9.118,1.8 9.118,3.722 9.83,4.434 35.366,4.434 ; 35.371,4.437 36.594,5.66 36.594,6.177 R40.1 ; R40.1 R41.1@36.666,7.099
VDDU1: C31.1 C32.1 U1.4 U1.6 | length 3.4
  Top Layer w0.254: U1.6 14.25,12.121 14.379,12.25 C32.1 ; U1.4 14.927,11.052 15.375,11.052 15.723,11.4 C31.1 15.737,11.513 C32.1@15.737,12.187
VDDU2: C41.1 C42.1 U2.4 U2.6 | length 3.6
  Top Layer w0.254: U2.6 36.592,12.121 36.737,12.266 37.846,12.266 38.1,12.012 C42.1 37.523,11.135 37.438,11.05 U2.4
pads on no net: FD1.0 FD2.0 FD3.0 Q1A. Q1B. Q2A. Q2B. Q3A. Q3B. Q4A. Q4B. SO1.1 SO2.1 SO3.1 SO4.1 SO5.1 U1.0 U1.1 U1.11 U1.15 U2.0 U2.1 U2.11 U2.15
copper on no net: | length 0
  Top Layer w0.254: 4.3,1.817 4.317,1.8
  Top Layer w0.4: 4.3,1.817 4.317,1.835

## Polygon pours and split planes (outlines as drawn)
SEC_RTN on Mid-Layer 1 "NONET_L-01_P-001" (solid, pour order 130): 34.997,9.5 39.5,9.5 39.5,13.65 35.01,13.65 34.997,13.637
SEC_RTN on Mid-Layer 1 "NONET_L-01_P-001" (solid, pour order 129): 12.972,9.5 17,9.5 17,13.624 16.974,13.65 16.926,13.602 12.957,13.602 12.957,9.55
SEC_SR2 on Mid-Layer 1 "NONET_L-01_P-001" (solid, pour order 125): 32,36.75 32,31.898 49.998,31.898 50,32 50,14.625 24.3,14.625 24.3,36.75
SEC_SR1 on Mid-Layer 1 "NONET_L-01_P-001" (solid, pour order 124): 8.238,31.754 8.238,36.773 8.184,36.828 16.05,36.828 16.05,31.79 24.05,31.828 24.05,14.643 0.05,14.643 0.05,31.716
SEC_RTN on Mid-Layer 1 "NONET_L-01_P-001" (solid, pour order 113): 44.85,15.737 44.85,14.621 43.942,14.621 43.55,14.23 43.55,13.563 31.55,13.563 31.55,15.625 31.633,15.708 32.642,15.708 33.75,15.737 33.75,14.65 32.933,14.65 32.685,14.402 32.685,14.25 42.358,14.25 42.65,14.542 42.65,15.528 42.859,15.737
SEC_RTN on Mid-Layer 1 "NONET_L-01_P-001" (solid, pour order 112): 21.833,15.743 22.3,15.743 22.3,14.584 21.833,14.584 21.283,14.034 21.283,13.563 9.413,13.563 9.287,13.563 9.287,15.436 9.593,15.743 11.343,15.743 11.343,14.643 10.481,14.643 10.481,14.385 10.483,14.383 10.483,14.25 20.283,14.25 20.45,14.417 20.45,15.666 20.527,15.743
SGND on Mid-Layer 1 "NONET_L-01_P-001" (solid, pour order 114): 0,13.25 49.685,13.25 49.685,3.389 0,3.389
SGND on Mid-Layer 4 "NONET_L-01_P-001" (solid, pour order 128): 0.321,13.278 0.321,3.422 50.17,3.422 50.171,3.421 50.271,3.521 50.271,13.278
SEC_SR1 on Mid-Layer 4 "NONET_L-01_P-001" (solid, pour order 127): 8.25,31.753 8.25,36.772 8.196,36.827 16.062,36.827 16.062,31.789 24.062,31.827 24.062,14.642 0.062,14.642 0.062,31.715
SEC_SR2 on Mid-Layer 4 "NONET_L-01_P-001" (solid, pour order 126): 32,36.69 32,31.838 49.998,31.838 50,31.94 50,14.565 24.3,14.565 24.3,36.69
SEC_SR2 on Mid-Layer 4 "NONET_L-01_P-001" (solid, pour order 123): 31.3,13.64 31.3,7.937 32.8,7.937 34.604,9.741 34.604,12.046 33.354,13.296 33.354,13.64
SEC_SR1 on Mid-Layer 4 "NONET_L-01_P-001" (solid, pour order 122): 8.846,13.643 8.846,8.05 10.346,8.05 12.15,9.854 12.15,12.1 10.9,13.35 10.9,13.65 10.893,13.643
SEC_SR2 on Mid-Layer 4 "NONET_L-01_P-001" (solid, pour order 110): 28.224,15.7 28.224,14.659 28.219,14.663 27.315,14.665 27.116,14.466 27.116,14.35 27.266,14.2 37.149,14.2 37.416,14.467 37.416,15.453 37.663,15.7 39.2,15.7 39.2,14.667 38.509,14.659 38.166,14.316 38.166,13.53 26.296,13.53 26.266,13.5 26.266,15.5 26.466,15.7
SEC_SR1 on Mid-Layer 4 "NONET_L-01_P-001" (solid, pour order 109): 16.416,15.7 16.974,15.7 16.974,14.667 16.167,14.667 16.141,14.641 15.866,14.366 15.866,13.63 3.996,13.63 3.966,13.6 3.966,15.293 4.373,15.7 5.316,15.7 5.95,15.7 5.95,14.641 5.933,14.659 5.021,14.654 4.816,14.45 5.016,14.25 14.799,14.25 15.116,14.567 15.116,15.266 15.55,15.7
SGND on Top Layer "NONET_L-01_P-001" (solid, pour order 117): -0.005,13.5 -0.005,3.389 49.844,3.389 49.845,3.388 49.945,3.488 49.945,13.5
SEC_SR2 on Top Layer "NONET_L-01_P-001" (solid, pour order 83): 32.25,16.317 32.25,14.633 27.78,14.633 27.78,20.75 33.349,20.75 33.349,16.317
SEC_SR2 on Top Layer "NONET_L-01_P-001" (solid, pour order 111): 44.376,16.298 43.389,16.298 43.389,14.65 38.906,14.65 38.906,15.973 38.906,20.823 44.376,20.823
PRE_54V on Top Layer "NONET_L-01_P-001" (solid, pour order 88): 27.694,16.241 27.612,16.322 26.713,16.322 26.713,14.65 25.097,14.65 25.097,20.367 27.694,20.366
SEC_RTN on Top Layer "NONET_L-01_P-001" (solid, pour order 70): 11.11,15.269 11.746,14.633 13.672,14.633 13.672,20.367 11.11,20.367
SEC_SR2 on Top Layer "NONET_L-01_P-001" (solid, pour order 89): 24.3,32.3 24.3,19.45 50,19.45 50,32.3
SEC_RTN on Top Layer "NONET_L-01_P-001" (solid, pour order 85): 33.391,14.633 35.95,14.633 35.95,20.367 33.391,20.367
PRE_54V on Top Layer "NONET_L-01_P-001" (solid, pour order 86): 38.75,16 38.744,15.994 38.744,14.633 36.1,14.633 36.1,20.367 38.75,20.367
SEC_RTN on Top Layer "NONET_L-01_P-001" (solid, pour order 87): 44.46,14.65 50.13,14.65 50.13,20.353 44.46,20.353
SEC_RTN on Top Layer "NONET_L-01_P-001" (solid, pour order 80): 41.267,3 41.267,0.267 48.733,0.267 48.733,3
PRE_54V on Top Layer "NONET_L-01_P-001" (solid, pour order 79): 31.267,3 31.267,0.267 38.733,0.267 38.733,3
PRE_54V on Top Layer "NONET_L-01_P-001" (solid, pour order 73): 5.462,16.288 5.092,15.918 4.421,15.918 4.421,15.208 3.845,14.633 0.1,14.633 0.1,20.353 5.462,20.353
SEC_SR1 on Top Layer "NONET_L-01_P-001" (solid, pour order 68): 11.058,16.096 9.981,16.096 9.979,16.094 9.979,14.633 5.517,14.633 5.517,21 11.058,21
PRE_54V on Top Layer "NONET_L-01_P-001" (solid, pour order 71): 16.598,16.133 16.383,15.918 15.531,15.918 15.531,14.633 13.807,14.633 13.807,20.367 16.598,20.367
SEC_SR1 on Top Layer "NONET_L-01_P-001" (solid, pour order 69): 22.168,16.007 21.093,16.007 21.089,16.003 21.091,16.001 21.091,14.633 16.66,14.633 16.66,21.2 22.168,21.2
SEC_RTN on Top Layer "NONET_L-01_P-001" (solid, pour order 72): 22.22,14.633 24.884,14.633 24.884,20.367 22.22,20.367
SEC_SR1 on Top Layer "NONET_L-01_P-001" (solid, pour order 60): 8.188,31.927 8.188,36.946 8.134,37 16,37 16,31.622 24,31.66 24,19.736 0,19.736 0,31.889
SGND on Bottom Layer "NONET_L-01_P-001" (solid, pour order 118): 0.115,13.4 0.115,3.393 49.964,3.393 49.965,3.392 50,13.4
SEC_SR1 on Bottom Layer "NONET_L-01_P-001" (solid, pour order 90): 5.628,18.815 5.633,18.81 6.259,18.81 6.259,16.19 5.009,16.19 5.009,14.65 9.951,14.65 9.951,16.316 11.031,16.316 11.031,20.997 5.628,20.997
SEC_SR2 on Bottom Layer "NONET_L-01_P-001" (solid, pour order 63): 38.88,15.691 38.853,15.718 38.46,15.718 38.46,14.65 43.363,14.65 43.363,16.324 44.35,16.324 44.35,20.85 38.88,20.85 38.88,16
SEC_RTN on Bottom Layer "NONET_L-01_P-001" (solid, pour order 66): 44.45,15.718 43.942,15.718 43.942,14.65 50.11,14.65 50.11,20.449 44.45,20.449
SEC_SR2 on Bottom Layer "NONET_L-01_P-001" (solid, pour order 62): 27.75,15.736 27.736,15.722 27.3,15.722 27.3,14.65 32.251,14.65 32.251,16.316 33.2,16.316 33.2,20.78 27.75,20.78
PRE_54V on Bottom Layer "NONET_L-01_P-001" (solid, pour order 65): 38.744,16.316 37.803,16.316 37.803,14.65 36.079,14.65 36.079,20.397 38.744,20.397 38.746,20.397 38.744,20.395
SEC_RTN on Bottom Layer "NONET_L-01_P-001" (solid, pour order 108): 22.25,15.736 21.797,15.736 21.75,15.689 21.75,14.65 24.893,14.65 24.893,20.372 22.322,20.372 22.25,20.3
SEC_SR1 on Bottom Layer "NONET_L-01_P-001" (solid, pour order 96): 0,32.3 0,20.1 23.68,20.1 23.68,32.3
SEC_RTN on Bottom Layer "NONET_L-01_P-001" (solid, pour order 92): 11.137,15.733 11.132,15.729 10.647,15.729 10.647,14.655 10.652,14.65 13.671,14.65 13.671,20.397 11.145,20.397 11.145,16.004 11.137,16.004
PRE_54V on Bottom Layer "NONET_L-01_P-001" (solid, pour order 95): 5.482,15.869 4.089,15.869 4.078,15.88 4.078,14.65 0.073,14.65 0.073,20.397 5.482,20.397
SEC_SR1 on Bottom Layer "NONET_L-01_P-001" (solid, pour order 91): 16.737,15.733 16.734,15.736 16.173,15.736 16.173,14.65 21.063,14.65 21.063,16.316 22.141,16.316 22.141,21.197 16.737,21.197
PRE_54V on Bottom Layer "NONET_L-01_P-001" (solid, pour order 93): 16.633,16.316 15.503,16.316 15.503,14.65 13.827,14.65 13.827,20.396 16.439,20.396 16.444,20.401 16.633,20.401
PRE_54V on Bottom Layer "NONET_L-01_P-001" (solid, pour order 81): 31.2,3.602 31.2,0.267 38.8,0.267 38.8,3.602
SEC_RTN on Bottom Layer "NONET_L-01_P-001" (solid, pour order 82): 41.246,3 41.246,0.267 48.712,0.267 48.712,3
PRE_54V on Bottom Layer "NONET_L-01_P-001" (solid, pour order 67): 27.596,16.285 26.693,16.285 26.693,14.65 25.1,14.65 25.1,20.536 27.596,20.536
SEC_RTN on Bottom Layer "NONET_L-01_P-001" (solid, pour order 64): 33.3,15.722 32.903,15.722 32.84,15.659 32.84,14.65 35.944,14.65 35.944,20.449 33.3,20.449
SEC_SR2 on Bottom Layer "NONET_L-01_P-001" (solid, pour order 61): 24,19.906 48.897,19.906 50,21.009 50,32 32,32 32,37 24,37 24,32
no net on Top Solder "NONET_L-01_P-001" (solid): 31,3 31,0 39,0 39,3 31,3
no net on Top Solder "NONET_L-01_P-001" (solid): 41,3 41,0 49,0 49,3 41,3
no net on Top Solder "NONET_L-01_P-001" (solid): 24,37 24,32 32,32 32,37
no net on Top Solder "NONET_L-01_P-001" (solid): 8,37 8,32 16,32 16,37
PRE_54V on Mid-Layer 3 (54V) "NONET_L-01_P-001" (solid, pour order 121): 38.782,3.72 49.95,3.72 49.95,31.921 0,31.921 0,3.38 31.267,3.38 31.3,3.348 31.247,3.294 31.247,-0.029 38.782,-0.029
no net on Bottom Solder "NONET_L-01_P-001" (solid): 40.979,3 40.979,0 48.979,0 48.979,3 40.979,3
no net on Bottom Solder "NONET_L-01_P-001" (solid): 31,3 31,0 39,0 39,3 31,3
no net on Bottom Solder "NONET_L-01_P-001" (solid): 8,37 8,32 16,32 16,37
no net on Bottom Solder "NONET_L-01_P-001" (solid): 24,37 24,32 32,32 32,37
SEC_RTN on Mid-Layer 2 (Gnd) "NONET_L-01_P-001" (solid, pour order 120): -0.025,32 -0.025,3.4 40.999,3.4 41.025,3.426 41.025,-0.1 49.025,-0.1 49.025,3.289 50.125,3.289 50.125,32

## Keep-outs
Mid-Layer 2 (Gnd):
  circle w0.135: c15.314,10.923 r2.25
  circle w0.135: c37.642,10.651 r2.25
Keep-Out Layer:
  the board outline again, w0.254

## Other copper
Top Layer:
  rectangle net SEC_SR2: 24.3,32 31.7,36.733
Bottom Layer:
  rectangle net SGND: 3.735,3.1 9.67,3.5
  rectangle net SEC_SR2: 42.687,19.471 46.23,20.171
  rectangle net SEC_RTN: 42.648,18.411 46.19,19.111
  rectangle net SEC_SR2: 42.715,17.564 46.257,18.264
  rectangle net SEC_RTN: 42.648,16.707 46.19,17.407
  rectangle net SEC_SR2: 42.743,15.864 46.285,16.564
  rectangle net PRE_54V: 37.141,19.503 40.684,20.203
  rectangle net SEC_SR2: 37.101,18.443 40.644,19.143
  rectangle net PRE_54V: 37.168,17.595 40.711,18.295
  rectangle net SEC_SR2: 37.101,16.738 40.644,17.438
  rectangle net PRE_54V: 37.197,15.896 40.739,16.596
  rectangle net SEC_SR2: 31.552,19.475 35.095,20.175
  rectangle net SEC_RTN: 31.512,18.415 35.055,19.115
  rectangle net SEC_SR2: 31.579,17.568 35.122,18.268
  rectangle net SEC_RTN: 31.512,16.711 35.055,17.411
  rectangle net SEC_SR2: 31.608,15.868 35.15,16.568
  rectangle net PRE_54V: 25.987,19.489 29.53,20.189
  rectangle net SEC_SR2: 25.948,18.429 29.49,19.129
  rectangle net PRE_54V: 26.015,17.582 29.557,18.282
  rectangle net SEC_SR2: 25.948,16.725 29.49,17.425
  rectangle net PRE_54V: 26.043,15.882 29.585,16.582
  rectangle net SEC_SR1: 20.462,19.489 24.004,20.189
  rectangle net SEC_RTN: 20.422,18.429 23.965,19.129
  rectangle net SEC_SR1: 20.489,17.582 24.032,18.282
  rectangle net SEC_RTN: 20.422,16.725 23.965,17.425
  rectangle net SEC_SR1: 20.517,15.882 24.06,16.582
  rectangle net PRE_54V: 14.884,19.486 18.427,20.186
  rectangle net SEC_SR1: 14.845,18.427 18.387,19.127
  rectangle net PRE_54V: 14.912,17.579 18.454,18.279
  rectangle net SEC_SR1: 14.845,16.722 18.387,17.422
  rectangle net PRE_54V: 14.94,15.88 18.482,16.58
  rectangle net SEC_SR1: 9.359,19.486 12.901,20.186
  rectangle net SEC_RTN: 9.319,18.427 12.861,19.127
  rectangle net SEC_SR1: 9.386,17.579 12.928,18.279
  rectangle net SEC_RTN: 9.319,16.722 12.861,17.422
  rectangle net SEC_SR1: 9.414,15.88 12.957,16.58
  rectangle net PRE_54V: 3.83,15.88 7.372,16.58
  rectangle net SEC_SR1: 3.735,16.722 7.277,17.422
  rectangle net PRE_54V: 3.802,17.579 7.344,18.279
  rectangle net SEC_SR1: 3.735,18.427 7.277,19.127
  rectangle net PRE_54V: 3.774,19.486 7.317,20.186
  rectangle net SEC_SR1: 8.3,32 15.7,36.7

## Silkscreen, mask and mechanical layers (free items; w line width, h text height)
Top Overlay:
  text "EPC95xx  B5xxx   HPE AP-2.1  FETS: EPC2302" at 17.045,3.639 h1
Bottom Overlay:
  text "EPC95xx  B5xxx   HPE AP-2.1  FETS: EPC2302" at 35.019,21.008 h1
Mechanical 1:
  lines w0.25: 0,32 0,3 ; 0,3 0,3
  lines w0.254: 0,3 1,3 1,0 9.994,0 9.994,3 31,3 31,0 39,0 39,3 41,3 41,0 49,0 49,3 50,3 50,29 50,32 ; 0,32 8,32 ; 8,32 8,32 ; 8,32 8,37 ; 8,37 8,37 ; 8,37 16,37 16,32 24,32 24,37 32,37 32,32 ; 32,32 32,32 ; 32,32 50,32 ; 50,32 50,32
